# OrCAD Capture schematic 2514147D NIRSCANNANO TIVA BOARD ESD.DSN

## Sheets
1 PAGE-01  TITLE: title: ESD, NIRscan Nano Tiva Board
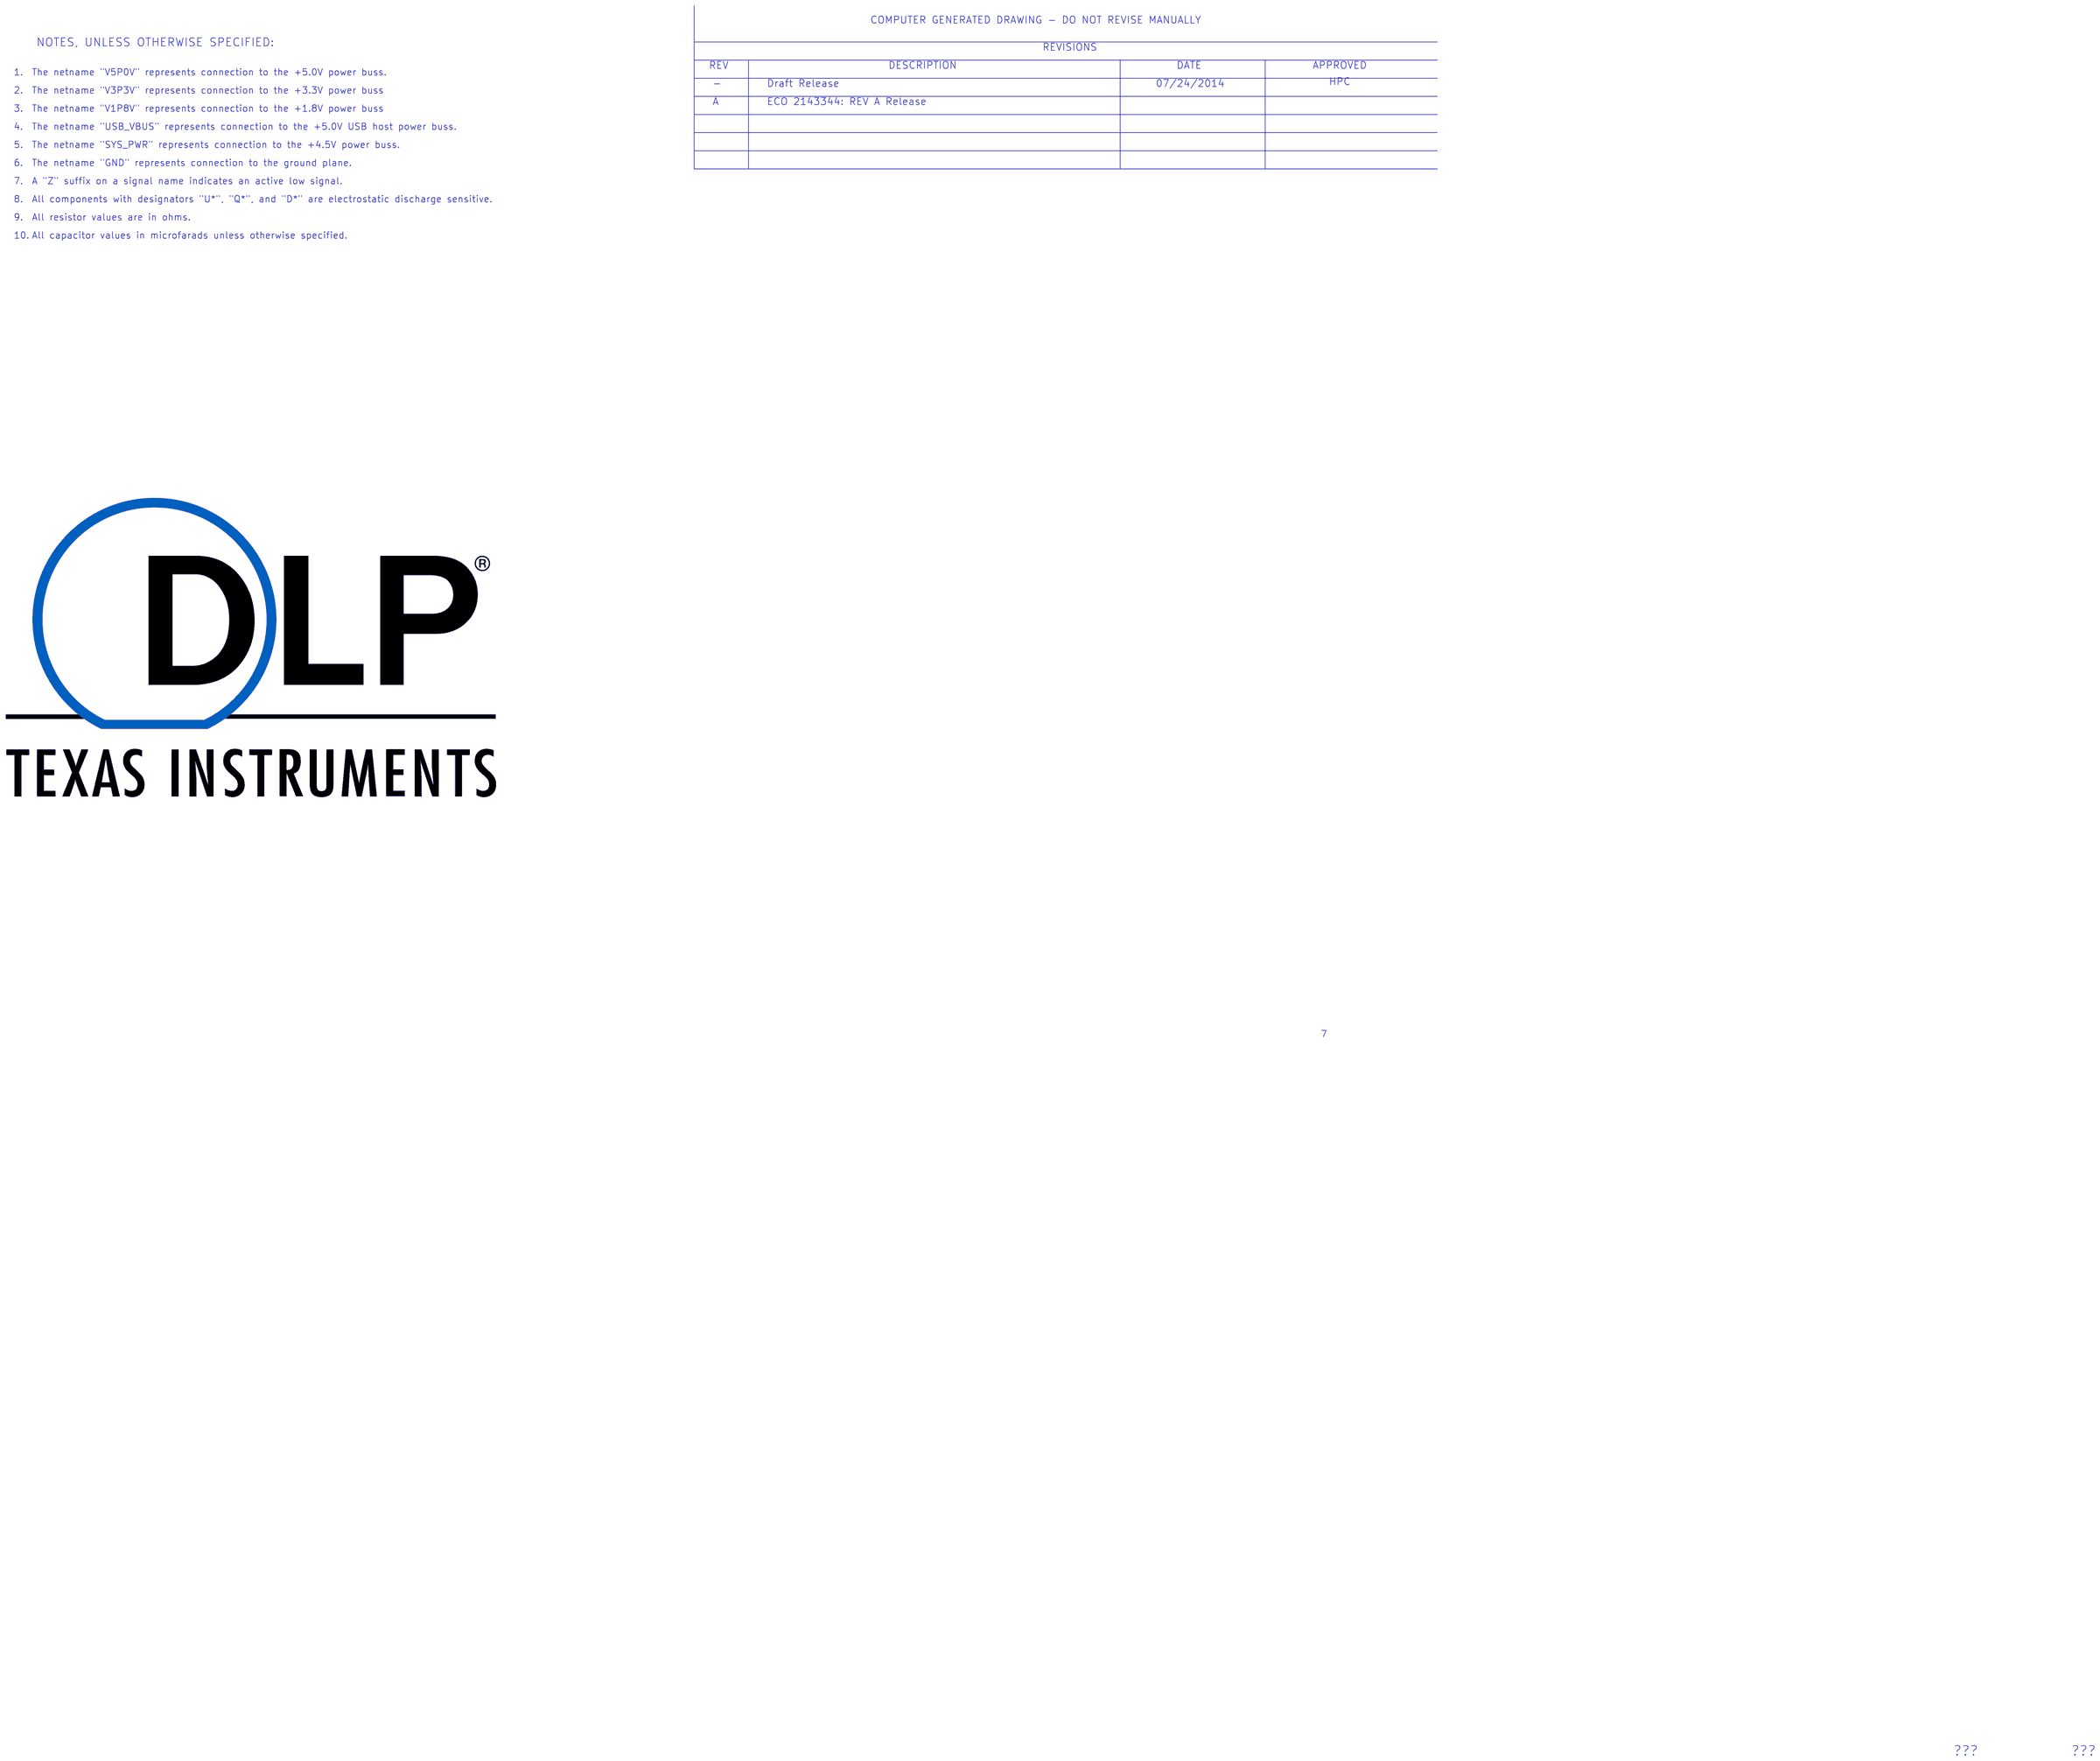
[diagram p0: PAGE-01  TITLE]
2 PAGE-02 TIVA EXTERNAL MEMORY: size A3
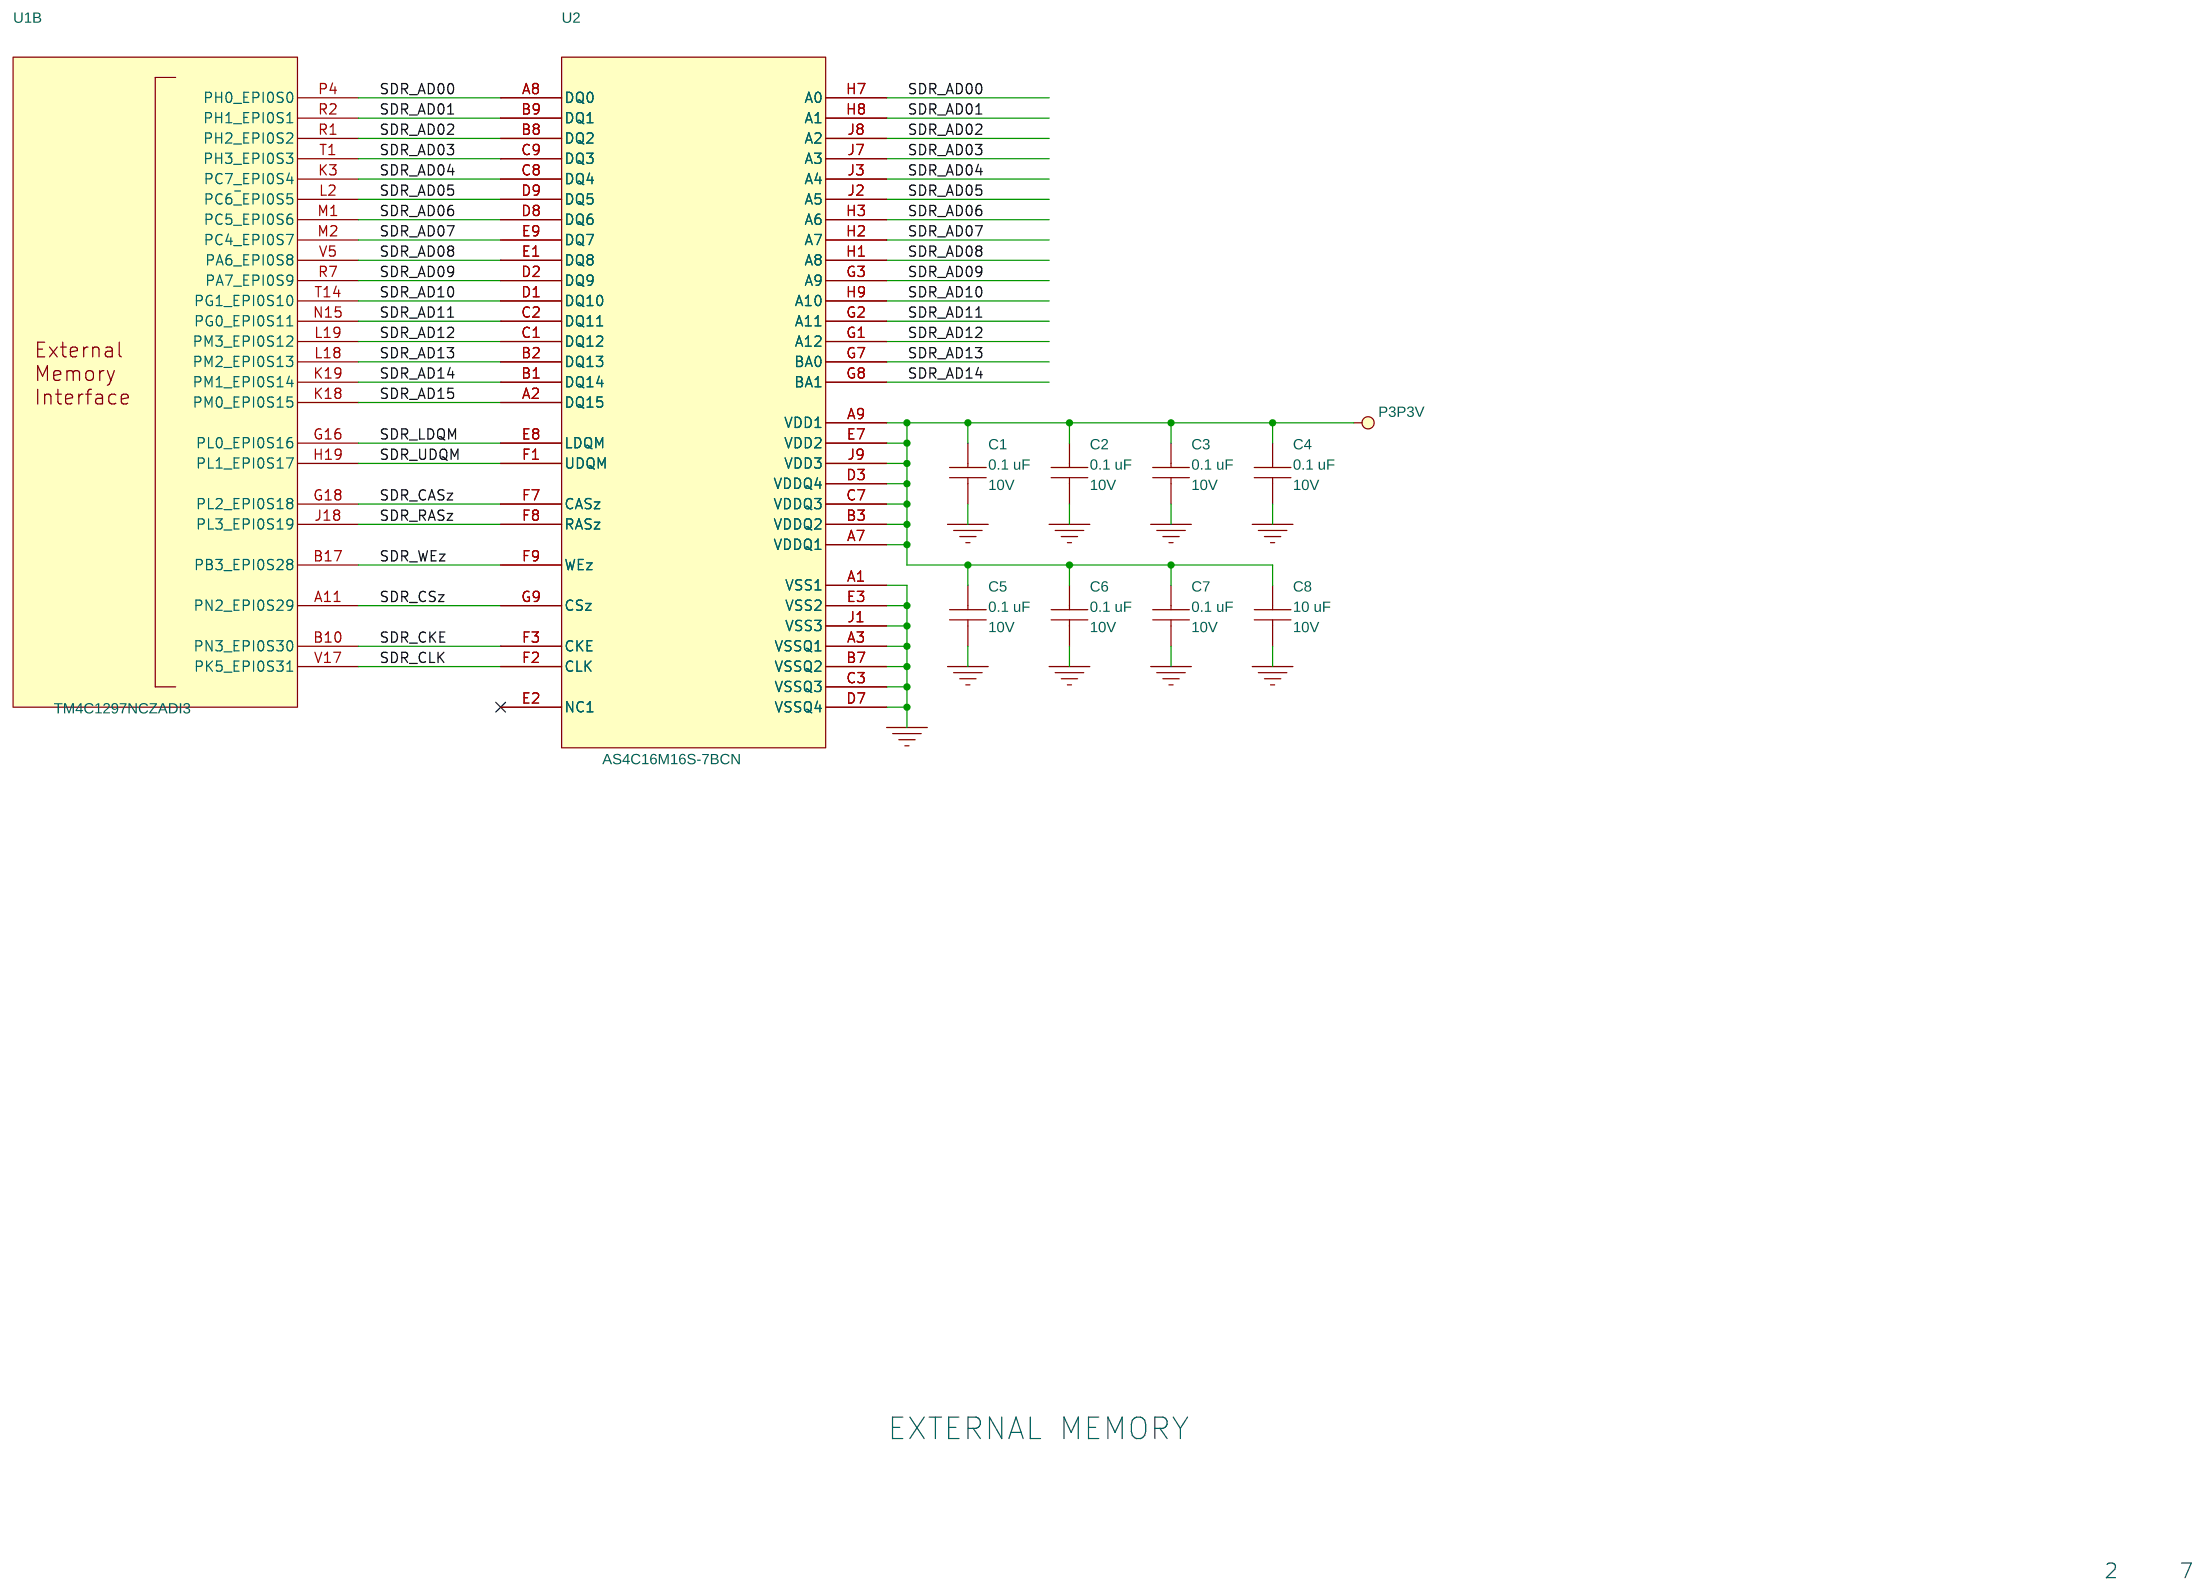
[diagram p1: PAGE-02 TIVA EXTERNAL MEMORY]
3 PAGE-03 TIVA PERIPHERALS: size A3
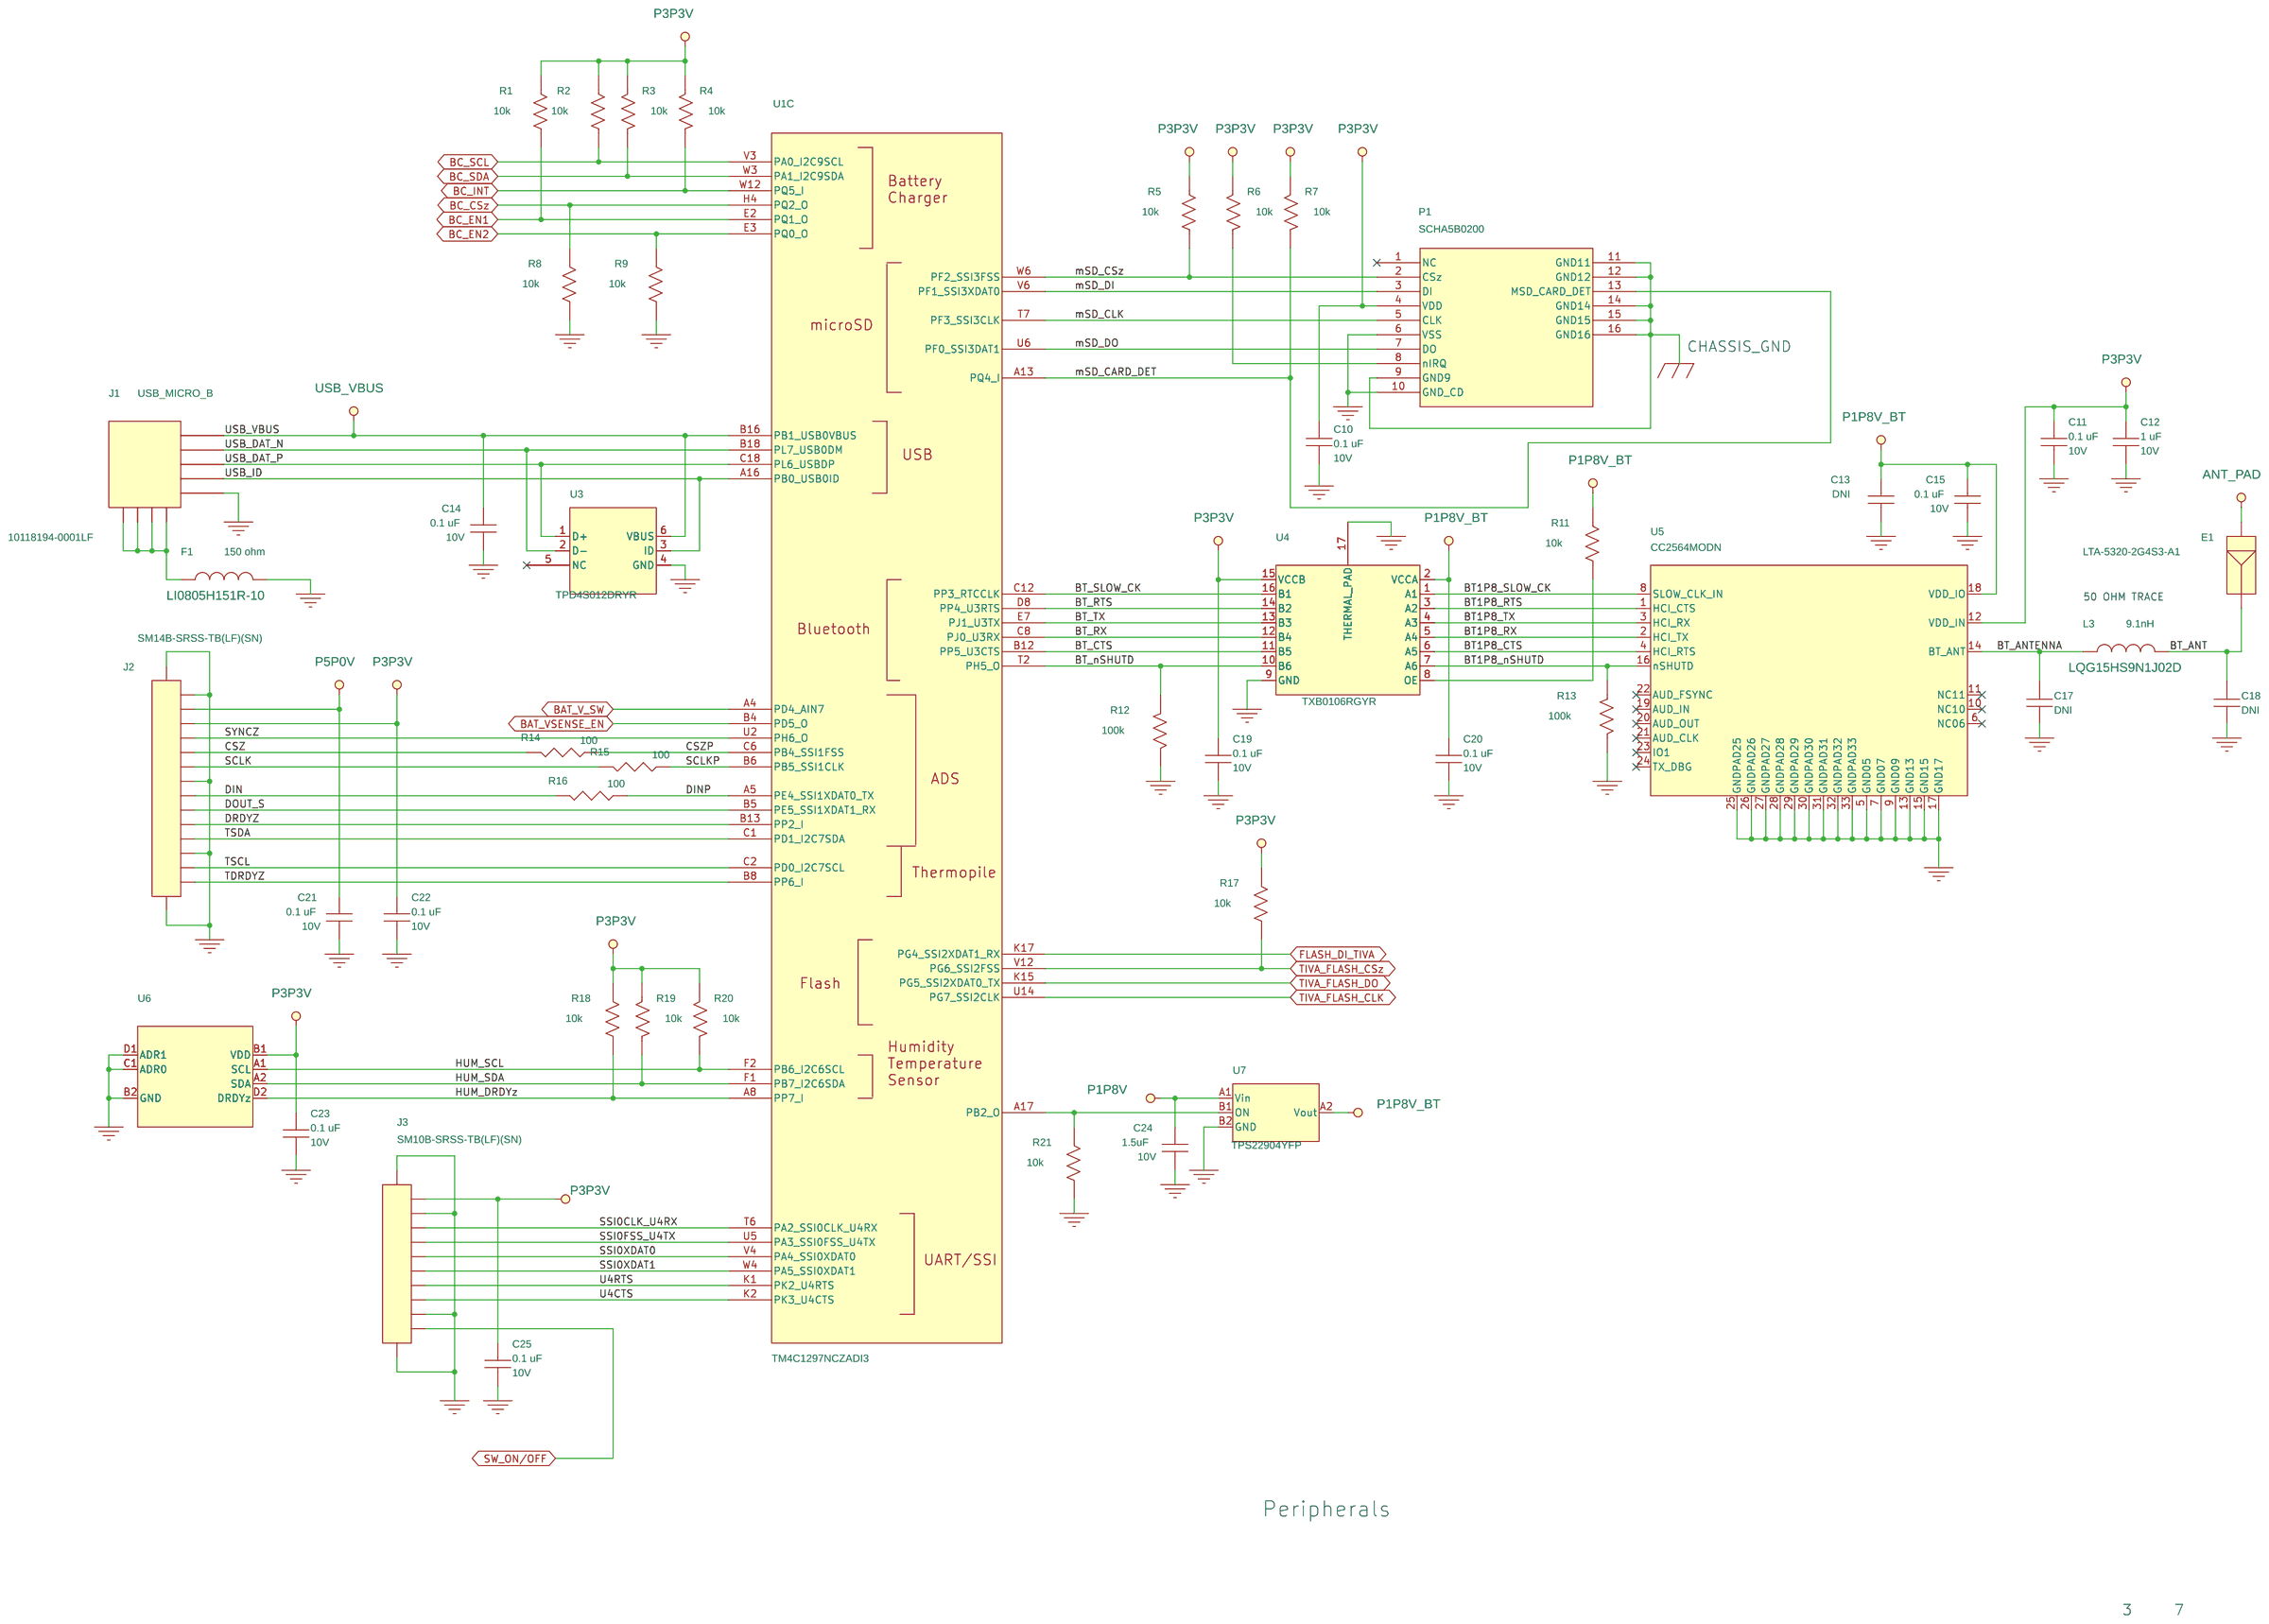
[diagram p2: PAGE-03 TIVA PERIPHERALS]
4 PAGE-04 TIVA POWER & MISC: size A3
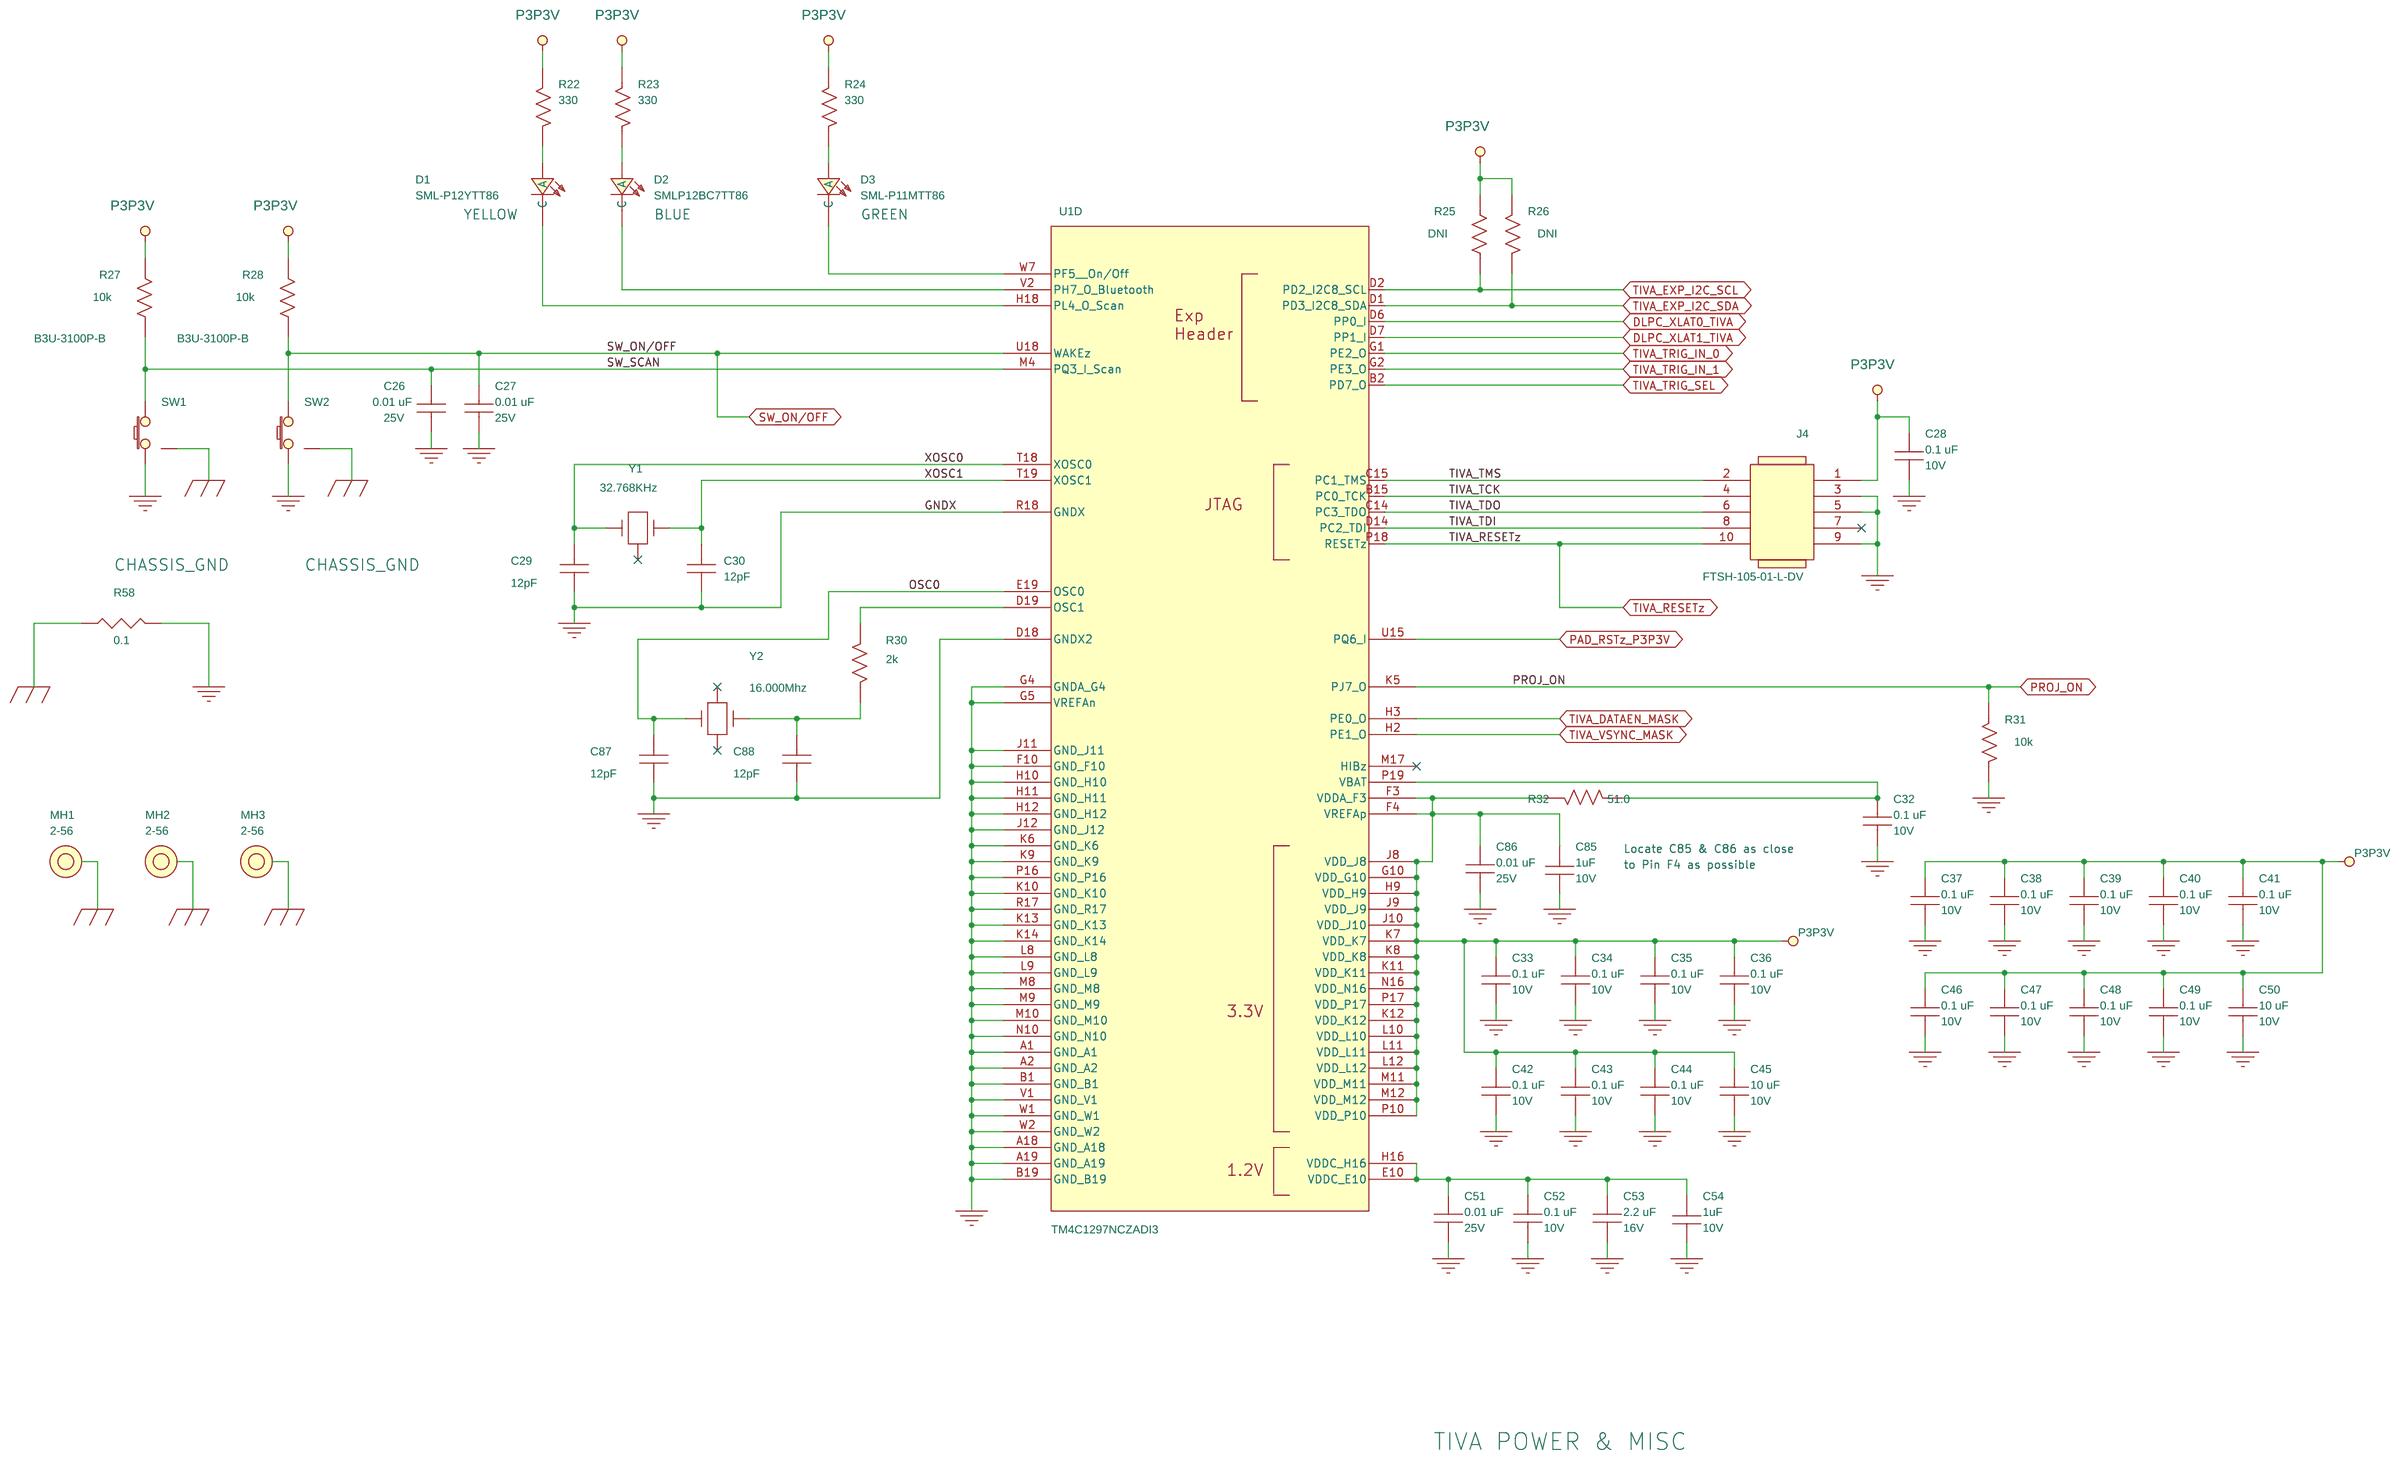
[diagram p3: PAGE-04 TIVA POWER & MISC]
5 PAGE-05 TIVA PARALLEL INTERFACE: size A3
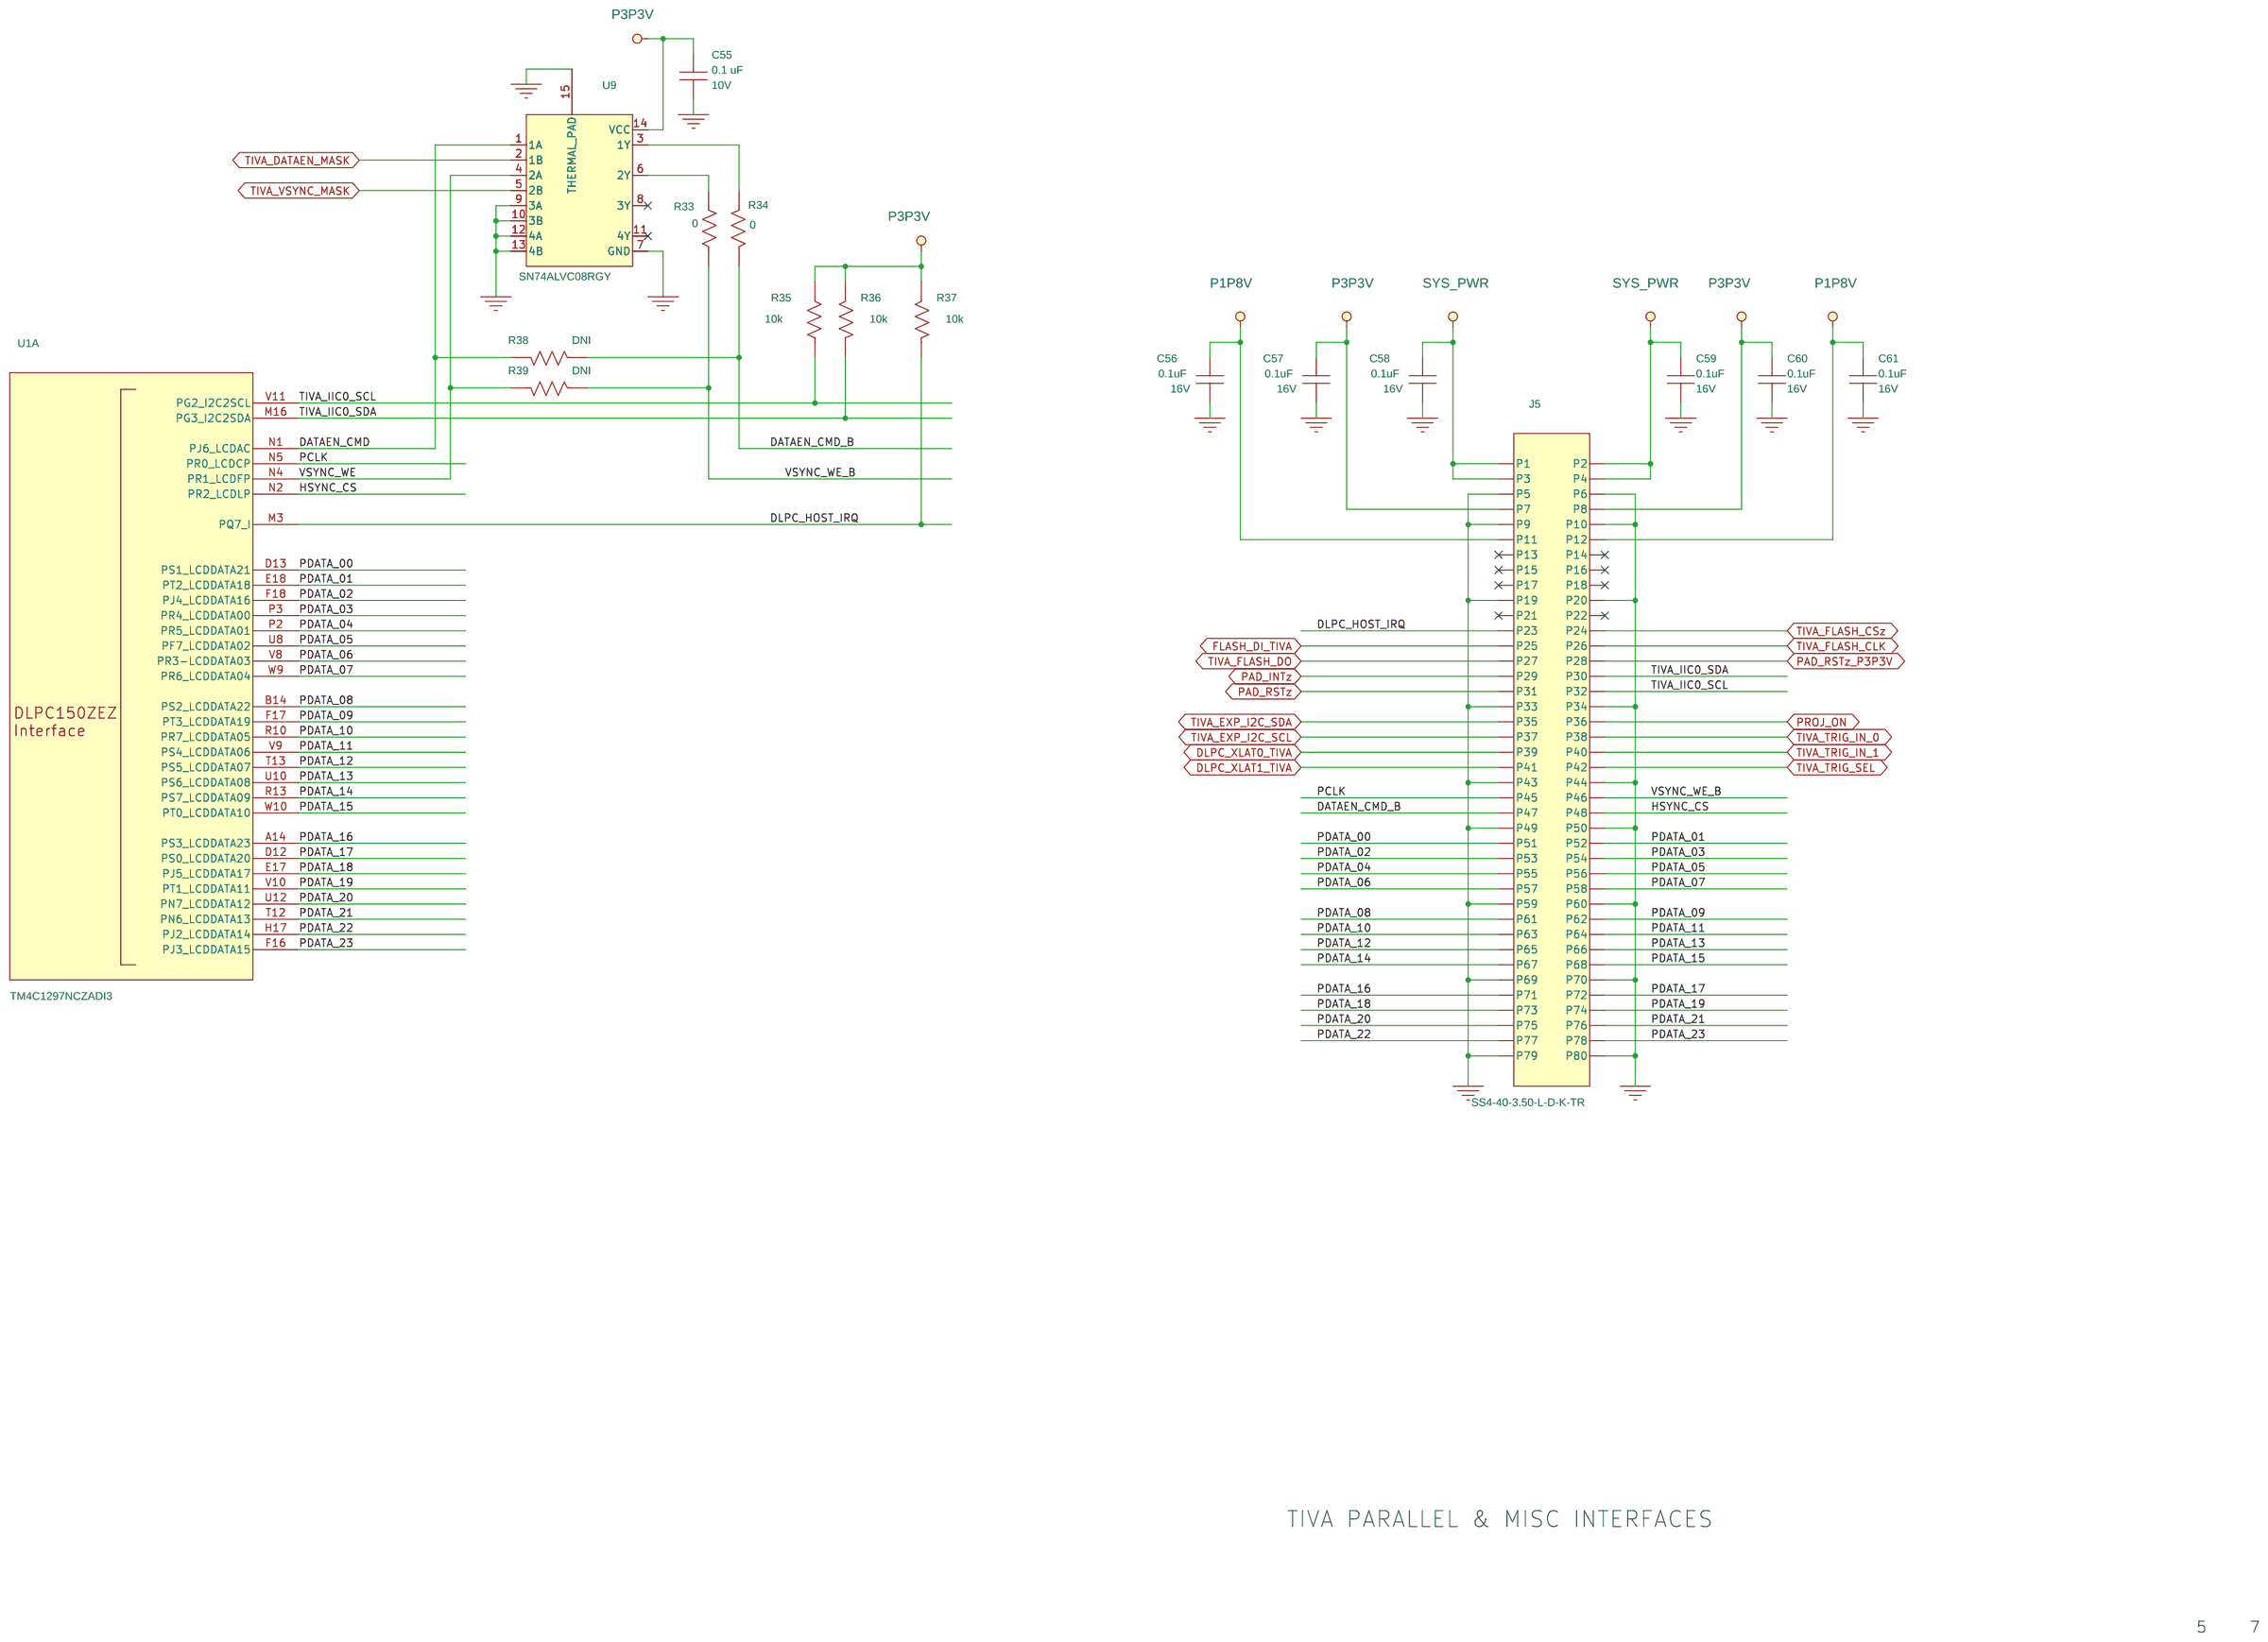
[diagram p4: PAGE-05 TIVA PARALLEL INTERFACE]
6 PAGE-06 POWER SUPPLIES: size A3
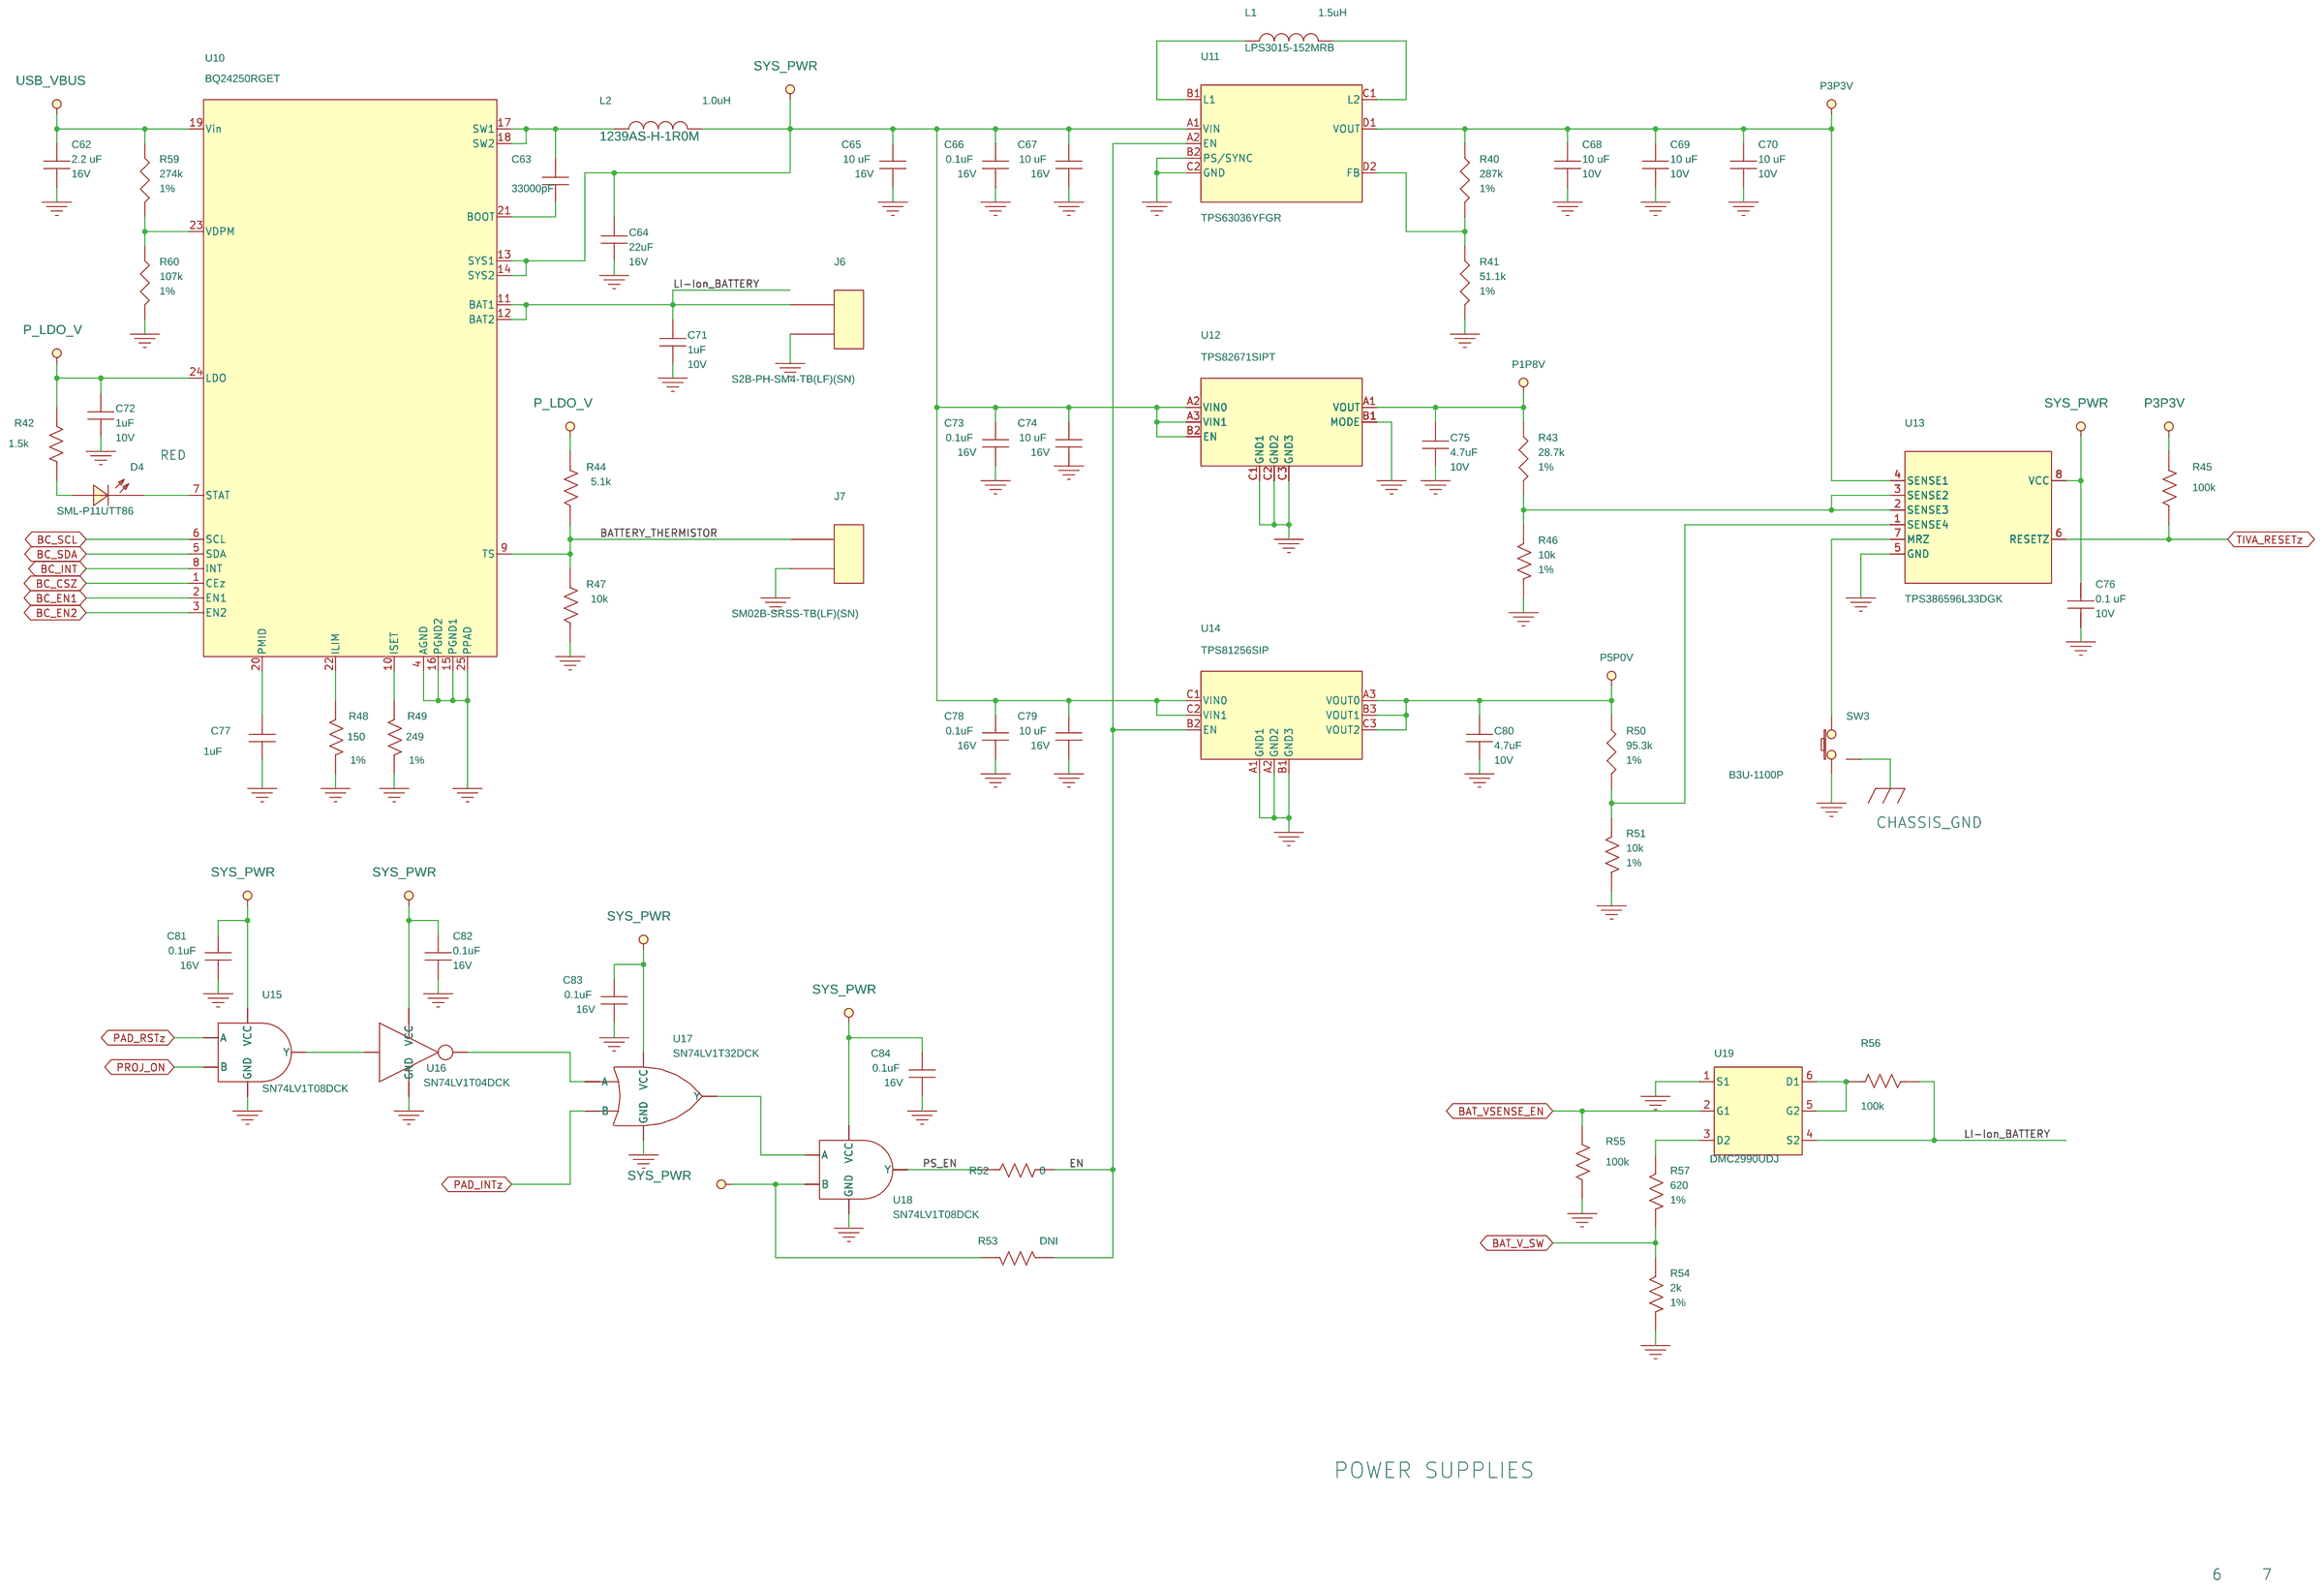
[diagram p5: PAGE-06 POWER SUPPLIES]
7 PAGE-07 REVISION HISTORY
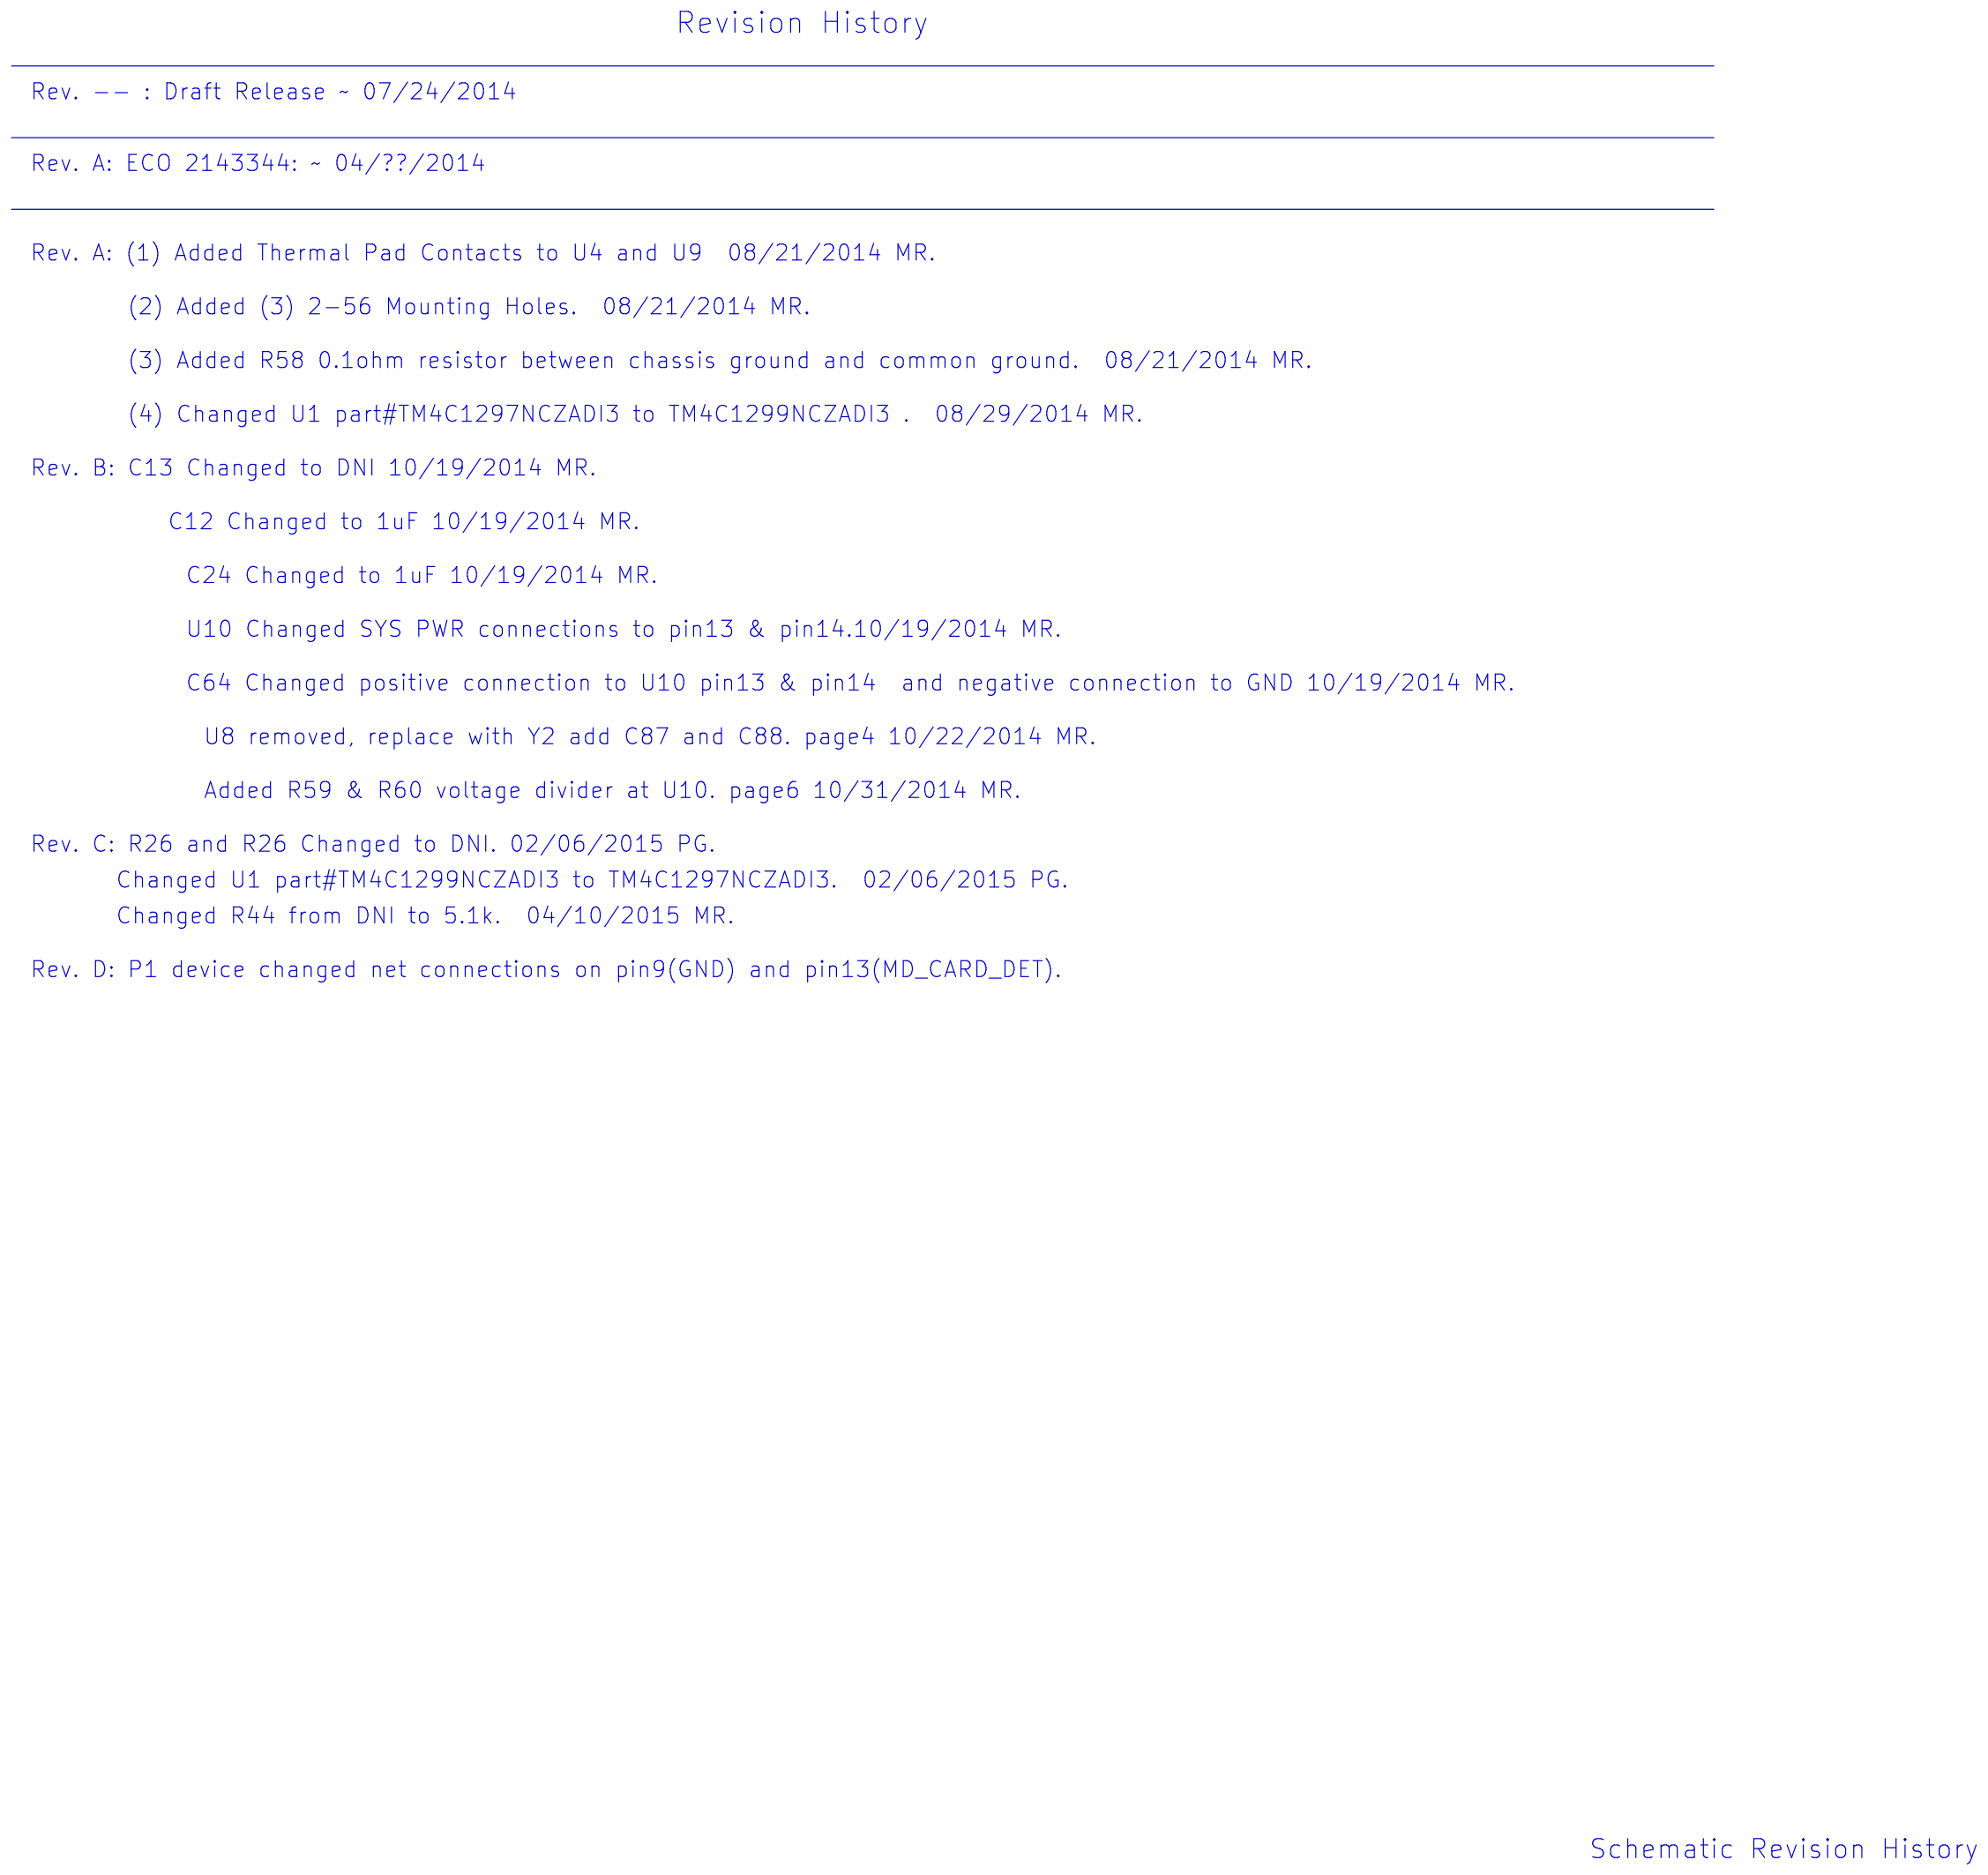
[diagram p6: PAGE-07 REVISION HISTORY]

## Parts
sheet PAGE-02 TIVA EXTERNAL MEMORY
C1  0.1 uF  [CAP_0402]
C2  0.1 uF  [CAP_0402]
C3  0.1 uF  [CAP_0402]
C4  0.1 uF  [CAP_0402]
C5  0.1 uF  [CAP_0402]
C6  0.1 uF  [CAP_0402]
C7  0.1 uF  [CAP_0402]
C8  10 uF  [CAP_0603]
U2  AS4C16M16S-7BCN  [TFBGA-54]
sheet PAGE-03 TIVA PERIPHERALS
C10  0.1 uF  [CAP_0402]
C11  0.1 uF  [CAP_0402]
C12  1 uF  [CAP_0603]
C13  DNI  [CAP_0402]
C14  0.1 uF  [CAP_0402]
C15  0.1 uF  [CAP_0402]
C17  DNI  [CAP_0201]
C18  DNI  [CAP_0201]
C19  0.1 uF  [CAP_0402]
C20  0.1 uF  [CAP_0402]
C21  0.1 uF  [CAP_0402]
C22  0.1 uF  [CAP_0402]
C23  0.1 uF  [CAP_0402]
C24  1.5uF  [CAP_0402]
C25  0.1 uF  [CAP_0402]
E1  LTA-5320-2G4S3-A1  [See_data_sheet]
F1  150 ohm  [0805]
J1  USB_MICRO_B  [See_data_sheet]
J2  SM14B-SRSS-TB(LF)(SN)  [CONN14_1p0mm]
J3  SM10B-SRSS-TB(LF)(SN)  [1p0mm_CONN10]
L3  9.1nH  [0402]
P1  SCHA5B0200  [SD-MICRO-SCHA5B0300]
R1  10k  [RES_0402]
R2  10k  [RES_0402]
R3  10k  [RES_0402]
R4  10k  [RES_0402]
R5  10k  [RES_0402]
R6  10k  [RES_0402]
R7  10k  [RES_0402]
R8  10k  [RES_0402]
R9  10k  [RES_0402]
R11  10k  [RES_0402]
R12  100k  [RES_0402]
R13  100k  [RES_0402]
R14  100  [RES_0402]
R15  100  [RES_0402]
R16  100  [RES_0402]
R17  10k  [RES_0402]
R18  10k  [RES_0402]
R19  10k  [RES_0402]
R20  10k  [RES_0402]
R21  10k  [RES_0402]
U1  TM4C1297NCZADI3  [ZAD_212]  (sections A,B,C,D)
U3  TPD4S012DRYR  [6-SON_DRY]
U4  TXB0106RGYR  [16-QFN]
U5  CC2564MODN  [TSSOP_38]
U6  HDC1000  [WCSP-8]
U7  TPS22904YFP  [DSBGA]
sheet PAGE-04 TIVA POWER & MISC
C26  0.01 uF  [CAP_0402]
C27  0.01 uF  [CAP_0402]
C28  0.1 uF  [CAP_0402]
C29  12pF  [CAP_0402]
C30  12pF  [CAP_0402]
C32  0.1 uF  [CAP_0402]
C33  0.1 uF  [CAP_0402]
C34  0.1 uF  [CAP_0402]
C35  0.1 uF  [CAP_0402]
C36  0.1 uF  [CAP_0402]
C37  0.1 uF  [CAP_0402]
C38  0.1 uF  [CAP_0402]
C39  0.1 uF  [CAP_0402]
C40  0.1 uF  [CAP_0402]
C41  0.1 uF  [CAP_0402]
C42  0.1 uF  [CAP_0402]
C43  0.1 uF  [CAP_0402]
C44  0.1 uF  [CAP_0402]
C45  10 uF  [CAP_0603]
C46  0.1 uF  [CAP_0402]
C47  0.1 uF  [CAP_0402]
C48  0.1 uF  [CAP_0402]
C49  0.1 uF  [CAP_0402]
C50  10 uF  [CAP_0603]
C51  0.01 uF  [CAP_0402]
C52  0.1 uF  [CAP_0402]
C53  2.2 uF  [CAP_0402]
C54  1uF  [CAP_0402]
C85  1uF  [CAP_0402]
C86  0.01 uF  [CAP_0402]
C87  12pF  [CAP_0402]
C88  12pF  [CAP_0402]
D1  SML-P12YTT86  [LED_0402]
D2  SMLP12BC7TT86  [LED_0402]
D3  SML-P11MTT86  [LED_0402]
J4  FTSH-105-01-L-DV  [0p050_2X5]
MH1  2-56  [pl_mtg_2_56_89d_260c]
MH2  2-56  [pl_mtg_2_56_89d_260c]
MH3  2-56  [pl_mtg_2_56_89d_260c]
R22  330  [RES_0402]
R23  330  [RES_0402]
R24  330  [RES_0402]
R25  DNI  [RES_0402]
R26  DNI  [RES_0402]
R27  10k  [RES_0402]
R28  10k  [RES_0402]
R30  2k  [RES_0402]
R31  10k  [RES_0402]
R32  51.0  [RES_0402]
R58  0.1  [0805]
SW1  B3U-3100P-B  [Micro_Switch]
SW2  B3U-3100P-B  [Micro_Switch]
Y1  32.768KHz  [CMR200T]
Y2  16.000Mhz  [CMR200T]
sheet PAGE-05 TIVA PARALLEL INTERFACE
C55  0.1 uF  [CAP_0402]
C56  0.1uF  [CAP_0402]
C57  0.1uF  [CAP_0402]
C58  0.1uF  [CAP_0402]
C59  0.1uF  [CAP_0402]
C60  0.1uF  [CAP_0402]
C61  0.1uF  [CAP_0402]
J5  SS4-40-3.50-L-D-K-TR  [CONN60_MEC8_M]
R33  0  [RES_0201]
R34  0  [RES_0201]
R35  10k  [RES_0402]
R36  10k  [RES_0402]
R37  10k  [RES_0402]
R38  DNI  [RES_0402]
R39  DNI  [RES_0402]
U9  SN74ALVC08RGY  [RGY]
sheet PAGE-06 POWER SUPPLIES
C62  2.2 uF  [CAP_0402]
C63  33000pF  [CAP_0402]
C64  22uF  [CAP_0805]
C65  10 uF  [CAP_0603]
C66  0.1uF  [CAP_0402]
C67  10 uF  [CAP_0603]
C68  10 uF  [CAP_0603]
C69  10 uF  [CAP_0603]
C70  10 uF  [CAP_0603]
C71  1uF  [CAP_0402]
C72  1uF  [CAP_0402]
C73  0.1uF  [CAP_0402]
C74  10 uF  [CAP_0603]
C75  4.7uF  [CAP_0402]
C76  0.1 uF  [CAP_0402]
C77  1uF  [CAP_0402]
C78  0.1uF  [CAP_0402]
C79  10 uF  [CAP_0603]
C80  4.7uF  [CAP_0402]
C81  0.1uF  [CAP_0402]
C82  0.1uF  [CAP_0402]
C83  0.1uF  [CAP_0402]
C84  0.1uF  [CAP_0402]
D4  SML-P11UTT86  [LED_0402]
J6  S2B-PH-SM4-TB(LF)(SN)  [CONN_2POS_2P0mm_RA]
J7  SM02B-SRSS-TB(LF)(SN)  [CONN_2POS_1P0mm_RA]
L1  1.5uH  [3p3mm_x_3p3mm]
L2  1.0uH  [2520]
R40  287k  [RES_0402]
R41  51.1k  [RES_0402]
R42  1.5k  [RES_0402]
R43  28.7k  [RES_0402]
R44  5.1k  [RES_0402]
R45  100k  [RES_0402]
R46  10k  [RES_0402]
R47  10k  [RES_0402]
R48  150  [RES_0402]
R49  249  [RES_0402]
R50  95.3k  [RES_0402]
R51  10k  [RES_0402]
R52  0  [RES_0201]
R53  DNI  [RES_0402]
R54  2k  [RES_0402]
R55  100k  [RES_0402]
R56  100k  [RES_0402]
R57  620  [RES_0402]
R59  274k  [RES_0402]
R60  107k  [RES_0402]
SW3  B3U-1100P  [Micro_Switch]
U10  BQ24250RGET  [24VQFN]
U11  TPS63036YFGR  [8WCSP]
U12  TPS82671SIPT  [8USIP]
U13  TPS386596L33DGK  [DGK]
U14  TPS81256SIP  [9USIP]
U15  SN74LV1T08DCK  [DCK]
U16  SN74LV1T04DCK  [DCK]
U17  SN74LV1T32DCK  [DCK]
U18  SN74LV1T08DCK  [DCK]
U19  DMC2990UDJ  [SOT963]

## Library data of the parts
C1-C7 C10 C11 C14 C15 C19-C23 C25 C28 C32-C44 C46-C49 C52 C55 C76 = CAP_NP: CAP CER 0.1UF 10V 10% X7R 0402; MFG: KEMET; Manufacturer: KEMET; Part Number: C0402C104K8RACTU; RATING: 10V; SOURCE: DIGI 399-3520-1-ND; TOLERANCE: 10%; Type: X7R
C8 C45 C50 C68-C70 = CAP_NP: CAP CER 10UF 10V 10% X5R 0603; MFG: TDK; Manufacturer: TDK; Part Number: C1608X5R1A106K080AC; RATING: 10V; SOURCE: DIGI 445-7486-1-ND; TOLERANCE: 10%; Type: X5R
U2 = AS4C16M16S-7BCN
C12 = CAP_NP: CAP CER 10UF 10V 10% X5R 0603; MFG: TDK; Manufacturer: TDK; Part Number: C1608X5R1A105K080AC; RATING: 10V; SOURCE: DIGI 445-1321-1-ND; TOLERANCE: 10%; Type: X5R
C13 = CAP_NP: CAP CER 10UF 6.3V 20% X5R 0402; MFG: TDK; Manufacturer: TDK; Part Number: C1005X5R0J106M050BC; RATING: 6.3V; SOURCE: DIGI 445-8920-1-ND; TOLERANCE: 20%; Type: X5R
C17 C18 = CAP_18PF_COG_50V_5%_0402: CAP CER ??PF 25V 0.5% NP0 0201; Manufacturer: TDK; Part Number: ??; RATING: 25V; SOURCE: DIGI ??; TOLERANCE: 0.5%; Type: NPO
C24 = CAP_NP: CAP CER 1.5uF 10V 10% X5R 0402; MFG: TDK; Manufacturer: TDK; Part Number: C1005X5R1A155K050BC; RATING: 10V; SOURCE: DIGI 445-7390-1-ND; TOLERANCE: 10%; Type: X5R
E1 = ANTENNA_CHIP: ANTENNA CHIP DIELECTRIC 2450MHZ; Manufacturer: Mag Layers; SOURCE: Mag Layers; Vendor: Mag Layers
F1 = PAS,INDUCTOR,_large: FERRITE 800mA 150 ohm 0402; Family: passive; Index PN: 1149; Lead Style: SMT; MFG: MURATA; Manufacturer: MURATA; P/D_NUM: LI0805H151R-10; Part Number: LI0805H151R-10; Part Specific: ?; RATING: 300mA; SOURCE: DIGI 240-2384-1-ND; Type: ferrite; VENDOR: DIGI 240-2384-1-ND
J1 = CON_USB_MICRO: CONN RCPT MICRO USB B 5POS THRU HOLE R/A; Manufacturer: FCI; Part Number: 10118194-0001LF; SOURCE: DIGI 609-4618-1-ND
J2 = CONN_14n_1p0mm: CONN HEADER SH 14POS TOP 1MM TIN; Manufacturer: JST; SOURCE: DIGI 455-1800-1-ND
J3 = CONN_10n_1p0mm: CONN HEADER SH 10POS SIDE 1MM TIN; Manufacturer: JST; SOURCE: DIGI 455-1810-1-ND
L3 = PAS,INDUCTOR,_large: INDUCTOR 9.1nH 300mA 0402; Family: passive; Index PN: 1149; Lead Style: SMT; MFG: MURATA; Manufacturer: MURATA; P/D_NUM: LQG15HS9N1J02D; Part Number: LQG15HS9N1J02D; Part Specific: ?; RATING: 300mA; SOURCE: RRFPD 1239AS-H-1R0M=P3; Type: inductor; VENDOR: DIGI 490-8390-1-ND
P1 = microSD_CONN_0: CONN MICRO SD CARD SOCKET; SOURCE: Mouser 688-SCHA5B0200
R1-R6 R8 R9 R11 R17-R21 R26-R28 R35 R46 = PAS,R,large: RES 10K OHM 1/10W 1% 0402 SMD; DigiKey: P10.0KLCT-ND; DigiReel: P10.0KLDKR-ND; Family: passive; Index PN: 680; Lead Style: SMT; MFG: Panasonic; Manufacturer: Panasonic; Material: chip; P/D_NUM: ERJ-2RKF1002X; Part Number: ERJ-2RKF1002X; Power: 1/16W; SOURCE: DIGI P10.0KLCT-ND; Tolerance: 1%; Type: resistor; VPC: 1/16W; Vendor: Panasonic
R7 R25 R31 R36 R37 R51 = PAS,R,large: RES 10K OHM 1/10W 1% 0402 SMD; Family: passive; Index PN: 680; Lead Style: SMT; MFG: Panasonic; Manufacturer: Panasonic; Material: chip; P/D_NUM: ERJ-2RKF1002X; Part Number: ERJ-2RKF1002X; Power: 1/16W; SOURCE: DIGI P10.0KLCT-ND; Tolerance: 1%; Type: resistor; VPC: 1/16W; Vendor: Panasonic
R12 R13 R45 R55 R56 = PAS,R,large: RES 100K OHM 1/10W 1% 0402 SMD; Family: passive; Index PN: 712; Lead Style: SMT; MFG: Panasonic; Manufacturer: Panasonic; Material: chip; P/D_NUM: ERJ-2RKF1003X; Part Number: ERJ-2RKF1003X; Power: 1/16W; SOURCE: DIGI P100KLCT-ND; TOLERANCE: 1%; Type: resistor; VPC: 1/16W; Vendor: Panasonic
R14-R16 = 1KR2F: RES 100 OHM 1/16W 1% 0402 SMD; MFG: Yageo; Manufacturer: ROHM; Manufacturer Part Number: MCR01MRTF1000; Part Number: MCR01MRTF1000; RATING: 1/16W; SOURCE: DIGI RHM100CDCT-ND; TOLERANCE: 1%
U1 = TM4C1297NCZADI3_7
U3 = TPD4S012_small: Manufacturer: Texas Instruments; SOURCE: DIGI 296-24244-1-ND
U4 = TXB0106RGYR_0
U5 = CC2564MODN
U6 = HDC1000
U7 = TPS22904
C26 C27 C51 C86 = CAP_NP: CAP CER 10000PF 25V 10% X5R 0402; MFG: KEMET; Manufacturer: TDK; Part Number: C1005X5R1E103K050BA; RATING: 25V; SOURCE: DIGI 445-7386-1-ND; TOLERANCE: 10%; Type: X5R
C29 C87 C88 = CAP_18PF_COG_50V_5%_0402: CAP CER 12PF 50V 5% NP0 0402; Desc: ?; Manufacturer: Murata; Part Number: GRM1555C1H120JA01D; RATING: 50V; SOURCE: DIGI 490-5924-1-ND; TOLERANCE: 5%; Type: NPO
C30 = CAP_18PF_COG_50V_5%_0402: CAP CER 12PF 50V 5% NP0 0402; Desc: CAP CER 18PF 50V 5% NP0 0402; Manufacturer: Murata; Part Number: GRM1555C1H120JA01D; RATING: 50V; SOURCE: DIGI 490-5924-1-ND; TOLERANCE: 5%; Type: NPO
C53 C62 = CAP_NP: CAP CER 2.2UF 16V 10% X5R 0402; MFG: MURATA; Manufacturer: TDK; Part Number: C1005X5R1C225K050BC; RATING: 16V; SOURCE: DIGI 445-9085-1-ND; TOLERANCE: 10%; Type: X5R
C54 C71 C72 C77 C85 = CAP_18PF_COG_50V_5%_0402: CAP CER 1UF 10V 20% X5R 0402; Manufacturer: TDK; Part Number: C1005X5R1A105M050BB; RATING: 10V; SOURCE: DIGI 445-4991-1-ND; TOLERANCE: 20%; Type: X5R
D1 = LED_v: LED YELLOW 0.2MM 130MCD 0402 SMD; Manufacturer: ROHM; SOURCE: DIGI 511-1595-1-ND
D2 = LED_v: LED 0402 BLUE 465NM TRANSPARENT; Manufacturer: ROHM; SOURCE: DIGI 511-1615-1-ND
D3 = LED_v: LED 0402 GREEN 54MW 20MA SMD; Manufacturer: ROHM; SOURCE: DIGI 511-1652-1-ND
J4 = HEADER_2X5_JTAG: 1.27mm SMT MICRO HEADER
MH1-MH3 = PL_MTG_2-56
R22-R24 = PAS,R,large: RES 300 OHM 1/10W 1% 0402 SMD; Family: passive; Index PN: 680; Lead Style: SMT; MFG: Panasonic; Manufacturer: Panasonic; Material: chip; P/D_NUM: ERJ-2RKF3000X; Part Number: ERJ-2RKF3000X; Power: 1/16W; SOURCE: DIGI P300LCT-ND; Tolerance: 1%; Type: resistor; VPC: 1/16W; Vendor: Panasonic
R30 = PAS,R,large: RES 2K OHM 1/10W 1% 0402 SMD; Family: passive; Index PN: 1167; Lead Style: SMT; Manufacturer: Panasonic; Part Number: ERJ-2RKF2001X; SOURCE: DIGI P2.00KLCT-ND; TOLERANCE: 1%; Type: resistor; VENDOR: Panasonic
R32 = PAS,R,large: RES 50.0 OHM 1/10W 1% 0402 SMD; Family: passive; Index PN: 1167; Lead Style: SMT; Manufacturer: Panasonic; Part Number: ERJ-2RKF51R0X; SOURCE: DIGI P51.0LCT-ND; TOLERANCE: 1%; Type: resistor; VENDOR: Panasonic
R58 = RES0805
SW1 SW2 = SWITCH,PUSH_BUTTON_SPST: SWITCH TACTILE SPST-NO 0.05A 12V; Manufacturer: Omron; RATING: 12VDC; SOURCE: DIGI SW1103CT-ND
Y1 = CRYS_32_768KHz: CRYSTAL 32.768KHZ 7PF SMD; Manufacturer: Citizen; Part Number: CMR200T-32.768KDZYT; SOURCE: DIGI 300-8736-1-ND
Y2 = CRYS_32_0: CRYSTAL 16.00MHZ 0.75mm SMD; Manufacturer: NDK; Mfr: NDK; MfrNum: NX3225GA- 16.000MHZ- STD-CRG-2; Part Number: NX3225GA- 16.000MHZ- STD-CRG-2; PartName: CRYSTAL 16.00MHZ 0.75mm SMD; SOURCE: DIGI 644-1157-1-ND; Vendor: NDK
C56-C61 C66 C73 C78 C81-C84 = CAP_NP: CAP CER 0.1UF 16V 10% X7R 0402; MFG: Murata; Manufacturer: Murata; Part Number: GRM155R71C104KA88D; RATING: 16V; SOURCE: DIGI 490-3261-1-ND; TOLERANCE: 10%; Type: X7R; VPC: 16V
J5 = CONN80_MEC8_M_0_SOCKET
R33 R34 R52 = PAS,R,large: RES 0.0 OHM 1/20W JUMP 0201 SMD; Family: passive; Index PN: 1178; Lead Style: SMT; MFG: Panasonic; Manufacturer: Panasonic; Material: chip; P/D_NUM: ERJ-1GE0R00C; Part Number: ERJ-1GE0R00C; SOURCE: DIGI P0.0AGCT-ND; Type: resistor; VENDOR: Panasonic; VPC: 1/20W
R38 R39 R53 = PAS,R,large: RES ?? OHM 1/10W 1% 0402 SMD; Family: passive; Index PN: 687; Lead Style: SMT; MFG: Panasonic; Material: chip; Part Specific: RES 0.0 OHM 1/16W 0402 SMD; Power: 1/16W; TOLERANCE: 1%; Type: resistor; VPC: 1/16W; Vendor: Panasonic
U9 = SN74ALVC08_0: IC GATE AND 4CH 2-INP 14-VQFN; Source: DIGI 296-13918-1-ND
C63 = CAP_18PF_COG_50V_5%_0402: CAP CER 0.033UF 50V 10% X5R 0402; Manufacturer: TDK; Part Number: C1005X5R1H333K050BB; RATING: 50V; SOURCE: DIGI 445-1238-1-ND; TOLERANCE: 10%; Type: X5R
C64 = CAP_18PF_COG_50V_5%_0402: CAP CER 22UF 16V 20% X5R 0805; Desc: ?; Manufacturer: TDK; Part Number: C2012X5R1C226M125AC; RATING: 16V; SOURCE: DIGI 445-7647-1-ND; TOLERANCE: 20%; Type: X5R
C65 C67 C74 C79 = CAP_NP: CAP CER 10UF 16V 20% X5R 0603; MFG: TDK; Manufacturer: TDK; Part Number: C1608X5R1C106M080AB; RATING: 16V; SOURCE: DIGI 445-9065-1-ND; TOLERANCE: 20%; Type: X5R
C75 C80 = CAP_18PF_COG_50V_5%_0402: CAP CER 4.7UF 10V 10% X5R 0402; Manufacturer: TDK; Part Number: C1005X5R1A475K050BC; RATING: 10V; SOURCE: DIGI 445-13820-1-ND; TOLERANCE: 10%; Type: X5R
D4 = LED_LTST-C150CKT_2: LED 0402 RED 50MW 20MA SMD; Manufacturer: ROHM; SOURCE: DIGI 511-1653-1-ND
J6 = CON2: CONN HEADER 2 POS 2.0MM R/A SMD; Manufacturer: JST; Source: DIGI 455-1749-1-ND
J7 = CON2: CONN HEADER 2 POS 1.0MM R/A SMD; Manufacturer: JST; Source: DIGI 455-1802-1-ND
L1 = INDUCTOR: INDUCTOR 1.5uH SHIELDED POWER; Manufacturer: Coilcraft; Part Number: LPS3015-152MRB; SOURCE: Mouser 994-LPS3015-152MRB
L2 = PAS,INDUCTOR,_large: INDUCTOR 1uH 20% 2520; Family: passive; Index PN: 1149; Lead Style: SMT; MFG: TOKO; Manufacturer: TOKO; P/D_NUM: LQM2HPN2R2MG0L; Part Number: 1239AS-H-1R0M; Part Specific: ?; RATING: 3AMP; SOURCE: RRFPD 1239AS-H-1R0M=P3; Tolerance: 20%; Type: inductor; VENDOR: ?
R40 = RESISTOR: RES 287K OHM 1/10W 1% 0402 SMD; Manufacturer: Panasonic; P/D_NUM: ERJ-2RKF2873X; Part Number: ERJ-2RKF2873X; SOURCE: DIGI P287KLCT-ND; TOLERANCE: 1%
R41 = RESISTOR: RES 51.1K OHM 1/10W 1% 0402 SM; Manufacturer: Panasonic; P/D_NUM: P51.1KLCT-ND; Part Number: P51.1KLCT-ND; SOURCE: DIGI P51.1KLCT-ND; TOLERANCE: 1%
R42 = PAS,R,large: RES 1.5K OHM 1/10W 1% 0402 SMD; Family: passive; Index PN: 680; Lead Style: SMT; MFG: Panasonic; Manufacturer: Panasonic; Material: chip; P/D_NUM: ERJ-2RKF1501X; Part Number: ERJ-2RKF1501X; Power: 1/16W; SOURCE: DIGI P1.50KLCT-ND; Tolerance: 1%; Type: resistor; VPC: 1/16W; Vendor: Panasonic
R43 = RESISTOR: RES 28.7K OHM 1/10W 1% 0402 SMD; Manufacturer: Panasonic; P/D_NUM: ERJ-2RKF2872X; Part Number: ERJ-2RKF2872X; SOURCE: DIGI P28.7KLCT-ND; TOLERANCE: 1%
R44 = PAS,R,large: RES SMD 5.1K OHM 5% 1/10W 0402; Family: passive; Index PN: 687; Lead Style: SMT; MFG: Panasonic; Material: chip; Part Number: ERJ-2GEJ512X; Part Specific: RES SMD 5.1K OHM 5% 1/10W 0402; Power: 1/10W; TOLERANCE: 5%; Type: resistor; VPC: 1/10W; Vendor: Panasonic
R47 = PAS,R,large: RES 10k OHM 1/10W 1% 0402 SMD; Family: passive; Index PN: 687; Lead Style: SMT; MFG: Panasonic; Material: chip; Part Number: ERJ-2RKF1002X; Part Specific: RES 10k OHM 1/16W 0402 SMD; Power: 1/16W; TOLERANCE: 1%; Type: resistor; VPC: 1/16W; Vendor: Panasonic
R48 = PAS,R,large: RES 150 OHM 1/10W 1% 0402 SMD; Family: passive; Index PN: 680; Lead Style: SMT; MFG: Panasonic; Manufacturer: Panasonic; Material: chip; P/D_NUM: ERJ-2RKF1500X; Part Number: ERJ-2RKF1500X; Power: 1/16W; SOURCE: DIGI P150LCT-ND; Tolerance: 1%; Type: resistor; VPC: 1/16W; Vendor: Panasonic
R49 = PAS,R,large: RES 249 OHM 1/10W 1% 0402 SMD; Family: passive; Index PN: 680; Lead Style: SMT; MFG: Panasonic; Manufacturer: Panasonic; Material: chip; P/D_NUM: ERJ-2RKF2490X; Part Number: ERJ-2RKF2490X; Power: 1/16W; SOURCE: DIGI P249LCT-ND; Tolerance: 1%; Type: resistor; VPC: 1/16W; Vendor: Panasonic
R50 = RESISTOR: RES 95.3K OHM 1/10W 1% 0402 SMD; Manufacturer: Panasonic; P/D_NUM: ERJ-2RKF9532X; Part Number: ERJ-2RKF9532X; SOURCE: DIGI P95.3KLCT-ND; Tolerance: 1%
R54 = PAS,R,large: RES 2K OHM 1/10W 1% 0402 SMD; Family: passive; Index PN: 680; Lead Style: SMT; MFG: Panasonic; Manufacturer: Panasonic; Material: chip; P/D_NUM: ERJ-2RKF2001X; Part Number: ERJ-2RKF2001X; Power: 1/16W; SOURCE: DIGI P2.00KLCT-ND; Tolerance: 1%; Type: resistor; VPC: 1/16W; Vendor: Panasonic
R57 = PAS,R,large: RES 620 OHM 1/10W 1% 0402 SMD; Family: passive; Index PN: 680; Lead Style: SMT; MFG: Panasonic; Manufacturer: Panasonic; Material: chip; P/D_NUM: ERJ-2RKF6200X; Part Number: ERJ-2RKF6200X; Power: 1/16W; SOURCE: DIGI P620LCT-ND; Tolerance: 1%; Type: resistor; VPC: 1/16W; Vendor: Panasonic
R59 = RESISTOR: RES 274K OHM 1/10W 1% 0402 SMD; Manufacturer: Panasonic; P/D_NUM: ERJ-2RKF2743X; Part Number: ERJ-2RKF2743X; SOURCE: DIGI P274KLCT-ND; TOLERANCE: 1%
R60 = RESISTOR: RES 107K OHM 1/10W 1% 0402 SMD; Manufacturer: KOA; P/D_NUM: ERJ-2RKF1073X; Part Number: ERJ-2RKF1073X; SOURCE: DIGI P107KLCT-ND; TOLERANCE: 1%
SW3 = SWITCH,PUSH_BUTTON_SPST: SWITCH TACTILE SPST-NO 0.05A 12V; Manufacturer: Omron; RATING: 12VDC; SOURCE: DIGI SW1021CT-ND
U10 = BQ24250RGET
U11 = TPS63036YFGR
U12 = TPS82671SIPT
U13 = TPS386596L33DGK
U14 = TPS81256SIPR
U15 U18 = SN74LV1T08: Source: MOUSER 595-SN74LV1T08DCKR
U16 = SN74LVC1G04DBV: IC SINGLE INVERTER GATE 5-SC70; MFG: Texas Instruments; Manufacturer: Texas Instruments; SOURCE: Mouser 595-SN74LV1T04DCKR
U17 = SN74LVC1G32: IC GATE OR 1CH 2-INP SC-70-5; MFG: Texas Instruments; Manufacturer: Texas Instruments; SOURCE: DIGI 296-37202-1-ND
U19 = DMC2990UDJ: IC COMPLEMENTARY PAIR MOSFET; Manufacturer: Texas Instruments; Mfr: Texas Instruments; Source: DIGI DMC2990UDJ-7DICT-ND; Vendor: DIGI DMC2990UDJ-7DICT-ND

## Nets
GND: C1.2 C2.2 C3.2 C4.2 C5.2 C6.2 C7.2 C8.2 C10.2 C11.2 C12.2 C13.2 C14.2 C15.2 C17.1 C18.1 C19.2 C20.2 C21.2 C22.2 C23.2 C24.2 C25.2 C26.2 C27.2 C28.2 C29.1 C30.1 C32.2 C33.2 C34.2 C35.2 C36.2 C37.2 C38.2 C39.2 C40.2 C41.2 C42.2 C43.2 C44.2 C45.2 C46.2 C47.2 C48.2 C49.2 C50.2 C51.2 C52.2 C53.2 C54.1 C55.2 C56.2 C57.2 C58.2 C59.2 C60.2 C61.2 C62.2 C64.1 C65.2 C66.2 C67.2 C68.2 C69.2 C70.2 C71.1 C72.1 C73.2 C74.2 C75.1 C76.2 C77.1 C78.2 C79.2 C80.1 C81.2 C82.2 C83.2 C84.2 C85.1 C86.2 C87.1 C88.1 F1.2 J1.5 J2.1 J2.7 J2.12 J2.15 J2.16 J3.2 J3.9 J3.11 J3.12 J4.3 J4.5 J4.9 J5.5(P5) J5.6(P6) J5.9(P9) J5.10(P10) J5.19(P19) J5.20(P20) J5.33(P33) J5.34(P34) J5.43(P43) J5.44(P44) J5.49(P49) J5.50(P50) J5.59(P59) J5.60(P60) J5.69(P69) J5.70(P70) J5.79(P79) J5.80(P80) J6.2 J7.2 P1.6(VSS) P1.10(GND_CD) R8.1(N1) R9.1(N1) R12.2(N2) R13.2(N2) R21.1(N1) R31.1(N1) R41.2 R46.1(N1) R47.2(N2) R48.1(N1) R49.1(N1) R51.1(N1) R54.1(N1) R55.2(N2) R58.2 R60.2 SW1.2 SW2.2 SW3.2 U1.A1(GND) U1.A2(GND) U1.A18(GND) U1.A19(GND) U1.B1(GND) U1.B19(GND) U1.D18(GNDX2) U1.F10(GND) U1.G4(GNDA) U1.G5(VREFAn) U1.H10(GND) U1.H11(GND) U1.H12(GND) U1.J11(GND) U1.J12(GND) U1.K6(GND) U1.K9(GND) U1.K10(GND) U1.K13(GND) U1.K14(GND) U1.L8(GND) U1.L9(GND) U1.M8(GND) U1.M9(GND) U1.M10(GND) U1.N10(GND) U1.P16(GND) U1.R17(GND) U1.R18(GNDX) U1.V1(GND) U1.W1(GND) U1.W2(GND) U2.A1(VSS1) U2.A3(VSSQ1) U2.B7(VSSQ2) U2.C3(VSSQ3) U2.D7(VSSQ4) U2.E3(VSS2) U2.J1(VSS3) U3.4(GND) U4.9(GND) U4.17(THERMAL_PAD) U5.5(GND05) U5.7(GND07) U5.9(GND09) U5.13(GND13) U5.15(GND15) U5.17(GND17) U5.25(GNDPAD25) U5.26(GNDPAD26) U5.27(GNDPAD27) U5.28(GNDPAD28) U5.29(GNDPAD29) U5.30(GNDPAD30) U5.31(GNDPAD31) U5.32(GNDPAD32) U5.33(GNDPAD33) U6.B2(GND) U6.C1(ADR0) U6.D1(ADR1) U7.B2(GND) U9.7(GND) U9.9(3A) U9.10(3B) U9.12(4A) U9.13(4B) U9.15(THERMAL_PAD) U10.4(AGND) U10.15(PGND1) U10.16(PGND2) U10.25(PPAD) U11.B2(PS/SYNC) U11.C2(GND) U12.B1(MODE) U12.C1(GND1) U12.C2(GND2) U12.C3(GND3) U13.5(GND) U14.A1(GND1) U14.A2(GND2) U14.B1(GND3) U15.3(GND) U16.3(GND) U17.3(GND) U18.3(GND) U19.1(S1)
GND_EARTH: MH1.1 MH2.1 MH3.1 P1.9(GND9) P1.11(GND11) P1.12(GND12) P1.14(GND14) P1.15(GND15) P1.16(GND16) R58.1 SW1.3 SW2.3 SW3.3
ANT_PAD: E1.2
BAT_V_SW: R54.2(N2) R57.1(N1) U1.A4(PD4_AIN7)
BAT_VSENSE_EN: R55.1(N1) U1.B4(PD5_O) U19.2(G1)
BATTERY_THERMISTOR: J7.1 R44.2(N2) R47.1(N1) U10.9(TS)
BC_CSZ: R8.2(N2) U1.H4(PQ2_O) U10.1(CEz)
BC_EN1: R1.1(N1) U1.E2(PQ1_O) U10.2(EN1)
BC_EN2: R9.2(N2) U1.E3(PQ0_O) U10.3(EN2)
BC_INT: R4.1(N1) U1.W12(PQ5_I) U10.8(INT)
BC_SCL: R2.1(N1) U1.V3(PA0_I2C9SCL) U10.6(SCL)
BC_SDA: R3.1(N1) U1.W3(PA1_I2C9SDA) U10.5(SDA)
BT1P8_CTS: U4.6(A5) U5.4(HCI_RTS)
BT1P8_nSHUTD: R13.1(N1) U4.7(A6) U5.16(nSHUTD)
BT1P8_RTS: U4.3(A2) U5.1(HCI_CTS)
BT1P8_RX: U4.5(A4) U5.2(HCI_TX)
BT1P8_SLOW_CK: U4.1(A1) U5.8(SLOW_CLK_IN)
BT1P8_TX: U4.4(A3) U5.3(HCI_RX)
BT_ANT: C18.2 E1.1 L3.2
BT_ANTENNA: C17.2 L3.1 U5.14(BT_ANT)
BT_CTS: U1.B12(PP5_U3CTS) U4.11(B5)
BT_nSHUTD: R12.1(N1) U1.T2(PH5_O) U4.10(B6)
BT_RTS: U1.D8(PP4_U3RTS) U4.14(B2)
BT_RX: U1.C8(PJ0_U3RX) U4.12(B4)
BT_SLOW_CK: U1.C12(PP3_RTCCLK) U4.16(B1)
BT_TX: U1.E7(PJ1_U3TX) U4.13(B3)
CSZ: J2.5 R14.1
CSZP: R14.2 U1.C6(PB4_SSI1FSS)
DATAEN_CMD: R38.1(N1) U1.N1(PJ6_LCDAC) U9.1(1A)
DATAEN_CMD_B: J5.47(P47) R34.2(N2) R38.2(N2)
DIN: J2.8 R16.1
DINP: R16.2 U1.A5(PE4_SSI1XDAT0_TX)
DLPC_HOST_IRQ: J5.23(P23) R37.1(N1) U1.M3(PQ7_I)
DLPC_XLAT0_TIVA: J5.39(P39) U1.D6(PP0_I)
DLPC_XLAT1_TIVA: J5.41(P41) U1.D7(PP1_I)
DOUT_S: J2.9 U1.B5(PE5_SSI1XDAT1_RX)
DRDYZ: J2.10 U1.B13(PP2_I)
EN: R52.1(N1) R53.2(N2) U11.A2(EN) U14.B2(EN)
FLASH_DI_TIVA: J5.25(P25) U1.K17(PG4_SSI2XDAT1_RX)
HSYNC_CS: J5.48(P48) U1.N2(PR2_LCDLP)
HUM_DRDYz: R18.1(N1) U1.A8(PP7_I) U6.D2(DRDYz)
HUM_SCL: R20.1(N1) U1.F2(PB6_I2C6SCL) U6.A1(SCL)
HUM_SDA: R19.1(N1) U1.F1(PB7_I2C6SDA) U6.A2(SDA)
LI-Ion_BATTERY: C71.2 J6.1 R56.2(N2) U10.11(BAT1) U10.12(BAT2) U19.4(S2)
mSD_CARD_DET: P1.13(MSD_CARD_DET) R7.1(N1) U1.A13(PQ4_I)
mSD_CLK: P1.5(CLK) U1.T7(PF3_SSI3CLK)
mSD_CSz: P1.2(CSz) R5.1(N1) U1.W6(PF2_SSI3FSS)
mSD_DI: P1.3(DI) U1.V6(PF1_SSI3XDAT0)
mSD_DO: P1.7(DO) U1.U6(PF0_SSI3DAT1)
OSC0: C87.2 U1.E19(OSC0) Y2.1
P1P8V: C24.1 C56.1 C61.1 C75.2 J5.11(P11) J5.12(P12) R43.1 U7.A1(Vin) U12.A1(VOUT)
P1P8V_BT: C13.1 C15.1 C20.1 R11.2(N2) U4.2(VCCA) U5.18(VDD_IO) U7.A2(Vout)
P3P3V: C1.1 C2.1 C3.1 C4.1 C5.1 C6.1 C7.1 C8.1 C10.1 C11.1 C12.1 C19.1 C22.1 C23.1 C25.1 C28.1 C33.1 C34.1 C35.1 C36.1 C37.1 C38.1 C39.1 C40.1 C41.1 C42.1 C43.1 C44.1 C45.1 C46.1 C47.1 C48.1 C49.1 C50.1 C55.1 C57.1 C60.1 C68.1 C69.1 C70.1 C85.2 C86.1 J2.3 J3.1 J4.1 J5.7(P7) J5.8(P8) P1.4(VDD) R1.2(N2) R2.2(N2) R3.2(N2) R4.2(N2) R5.2(N2) R6.2(N2) R7.2(N2) R17.2(N2) R18.2(N2) R19.2(N2) R20.2(N2) R22.2(N2) R23.2(N2) R24.2(N2) R25.2(N2) R26.2(N2) R27.2(N2) R28.2(N2) R32.2(N2) R35.2(N2) R36.2(N2) R37.2(N2) R40.1 R45.1(N1) U1.F3(VDDA) U1.F4(VREFAp) U1.G10(VDD) U1.H9(VDD) U1.J8(VDD) U1.J9(VDD) U1.J10(VDD) U1.K7(VDD) U1.K8(VDD) U1.K11(VDD) U1.K12(VDD) U1.L10(VDD) U1.L11(VDD) U1.L12(VDD) U1.M11(VDD) U1.M12(VDD) U1.N16(VDD) U1.P10(VDD) U1.P17(VDD) U2.A7(VDDQ1) U2.A9(VDD1) U2.B3(VDDQ2) U2.C7(VDDQ3) U2.D3(VDDQ4) U2.E7(VDD2) U2.J9(VDD3) U4.15(VCCB) U5.12(VDD_IN) U6.B1(VDD) U9.14(VCC) U11.D1(VOUT) U13.4(SENSE1)
P5P0V: C21.1 C80.2 J2.2 R50.1 U14.A3(VOUT0) U14.B3(VOUT1) U14.C3(VOUT2)
P_LDO_V: C72.2 R42.2(N2) R44.1(N1) U10.24(LDO)
PAD_INTz: J5.29(P29) U17.2(B)
PAD_RSTz: J5.31(P31) U15.1(A)
PAD_RSTz_P3P3V: J5.28(P28) U1.U15(PQ6_I)
PCLK: J5.45(P45) U1.N5(PR0_LCDCP)
PDATA_00: J5.51(P51) U1.D13(PS1_LCDDATA21)
PDATA_01: J5.52(P52) U1.E18(PT2_LCDDATA18)
PDATA_02: J5.53(P53) U1.F18(PJ4_LCDDATA16)
PDATA_03: J5.54(P54) U1.P3(PR4_LCDDATA00)
PDATA_04: J5.55(P55) U1.P2(PR5_LCDDATA01)
PDATA_05: J5.56(P56) U1.U8(PF7_LCDDATA02)
PDATA_06: J5.57(P57) U1.V8(PR3-LCDDATA03)
PDATA_07: J5.58(P58) U1.W9(PR6_LCDDATA04)
PDATA_08: J5.61(P61) U1.B14(PS2_LCDDATA22)
PDATA_09: J5.62(P62) U1.F17(PT3_LCDDATA19)
PDATA_10: J5.63(P63) U1.R10(PR7_LCDDATA05)
PDATA_11: J5.64(P64) U1.V9(PS4_LCDDATA06)
PDATA_12: J5.65(P65) U1.T13(PS5_LCDDATA07)
PDATA_13: J5.66(P66) U1.U10(PS6_LCDDATA08)
PDATA_14: J5.67(P67) U1.R13(PS7_LCDDATA09)
PDATA_15: J5.68(P68) U1.W10(PT0_LCDDATA10)
PDATA_16: J5.71(P71) U1.A14(PS3_LCDDATA23)
PDATA_17: J5.72(P72) U1.D12(PS0_LCDDATA20)
PDATA_18: J5.73(P73) U1.E17(PJ5_LCDDATA17)
PDATA_19: J5.74(P74) U1.V10(PT1_LCDDATA11)
PDATA_20: J5.75(P75) U1.U12(PN7_LCDDATA12)
PDATA_21: J5.76(P76) U1.T12(PN6_LCDDATA13)
PDATA_22: J5.77(P77) U1.H17(PJ2_LCDDATA14)
PDATA_23: J5.78(P78) U1.F16(PJ3_LCDDATA15)
PROJ_ON: J5.36(P36) R31.2(N2) U1.K5(PJ7_O) U15.2(B)
PS_EN: R52.2(N2) U18.4(Y)
SCLK: J2.6 R15.1
SCLKP: R15.2 U1.B6(PB5_SSI1CLK)
SDR_AD00: U1.P4(PH0_EPI0S0) U2.A8(DQ0) U2.H7(A0)
SDR_AD01: U1.R2(PH1_EPI0S1) U2.B9(DQ1) U2.H8(A1)
SDR_AD02: U1.R1(PH2_EPI0S2) U2.B8(DQ2) U2.J8(A2)
SDR_AD03: U1.T1(PH3_EPI0S3) U2.C9(DQ3) U2.J7(A3)
SDR_AD04: U1.K3(PC7_EPI0S4) U2.C8(DQ4) U2.J3(A4)
SDR_AD05: U1.L2(PC6~{_}EPI0S5) U2.D9(DQ5) U2.J2(A5)
SDR_AD06: U1.M1(PC5_EPI0S6) U2.D8(DQ6) U2.H3(A6)
SDR_AD07: U1.M2(PC4_EPI0S7) U2.E9(DQ7) U2.H2(A7)
SDR_AD08: U1.V5(PA6_EPI0S8) U2.E1(DQ8) U2.H1(A8)
SDR_AD09: U1.R7(PA7_EPI0S9) U2.D2(DQ9) U2.G3(A9)
SDR_AD10: U1.T14(PG1_EPI0S10) U2.D1(DQ10) U2.H9(A10)
SDR_AD11: U1.N15(PG0_EPI0S11) U2.C2(DQ11) U2.G2(A11)
SDR_AD12: U1.L19(PM3_EPI0S12) U2.C1(DQ12) U2.G1(A12)
SDR_AD13: U1.L18(PM2_EPI0S13) U2.B2(DQ13) U2.G7(BA0)
SDR_AD14: U1.K19(PM1_EPI0S14) U2.B1(DQ14) U2.G8(BA1)
SDR_AD15: U1.K18(PM0_EPI0S15) U2.A2(DQ15)
SDR_CASz: U1.G18(PL2_EPI0S18) U2.F7(CASz)
SDR_CKE: U1.B10(PN3_EPI0S30) U2.F3(CKE)
SDR_CLK: U1.V17(PK5_EPI0S31) U2.F2(CLK)
SDR_CSz: U1.A11(PN2_EPI0S29) U2.G9(CSz)
SDR_LDQM: U1.G16(PL0_EPI0S16) U2.E8(LDQM)
SDR_RASz: U1.J18(PL3_EPI0S19) U2.F8(RASz)
SDR_UDQM: U1.H19(PL1_EPI0S17) U2.F1(UDQM)
SDR_WEz: U1.B17(PB3_EPI0S28) U2.F9(WEz)
SSI0CLK_U4RX: J3.3 U1.T6(PA2_SSI0CLK_U4RX)
SSI0FSS_U4TX: J3.4 U1.U5(PA3_SSI0FSS_U4TX)
SSI0XDAT0: J3.5 U1.V4(PA4_SSI0XDAT0)
SSI0XDAT1: J3.6 U1.W4(PA5_SSI0XDAT1)
SW_ON/OFF: C27.1 J3.10 R28.1(N1) SW2.1 U1.U18(WAKEz)
SW_SCAN: C26.1 R27.1(N1) SW1.1 U1.M4(PQ3_I_Scan)
SYNCZ: J2.4 U1.U2(PH6_O)
SYS_PWR: C58.1 C59.1 C64.2 C65.1 C66.1 C67.1 C73.1 C74.1 C76.1 C78.1 C79.1 C81.1 C82.1 C83.1 C84.1 J5.1(P1) J5.2(P2) J5.3(P3) J5.4(P4) L2.2 R53.1(N1) U10.13(SYS1) U10.14(SYS2) U11.A1(VIN) U12.A2(VIN0) U12.A3(VIN1) U12.B2(EN) U13.8(VCC) U14.C1(VIN0) U14.C2(VIN1) U15.5(VCC) U16.5(VCC) U17.5(VCC) U18.2(B) U18.5(VCC)
TDRDYZ: J2.14 U1.B8(PP6_I)
TIVA_DATAEN_MASK: U1.H3(PE0_O) U9.2(1B)
TIVA_EXP_I2C_SCL: J5.37(P37) R25.1(N1) U1.D2(PD2_I2C8_SCL)
TIVA_EXP_I2C_SDA: J5.35(P35) R26.1(N1) U1.D1(PD3_I2C8_SDA)
TIVA_FLASH_CLK: J5.26(P26) U1.U14(PG7_SSI2CLK)
TIVA_FLASH_CSz: J5.24(P24) R17.1(N1) U1.V12(PG6_SSI2FSS)
TIVA_FLASH_DO: J5.27(P27) U1.K15(PG5_SSI2XDAT0_TX)
TIVA_IIC0_SCL: J5.32(P32) R35.1(N1) U1.V11(PG2_I2C2SCL)
TIVA_IIC0_SDA: J5.30(P30) R36.1(N1) U1.M16(PG3_I2C2SDA)
TIVA_RESETz: J4.10 R45.2(N2) U1.P18(RESETz) U13.6(RESETZ)
TIVA_TCK: J4.4 U1.B15(PC0_TCK)
TIVA_TDI: J4.8 U1.D14(PC2_TDI)
TIVA_TDO: J4.6 U1.C14(PC3_TDO)
TIVA_TMS: J4.2 U1.C15(PC1_TMS)
TIVA_TRIG_IN_0: J5.38(P38) U1.G1(PE2_O)
TIVA_TRIG_IN_1: J5.40(P40) U1.G2(PE3_O)
TIVA_TRIG_SEL: J5.42(P42) U1.B2(PD7_O)
TIVA_VSYNC_MASK: U1.H2(PE1_O) U9.5(2B)
TSCL: J2.13 U1.C2(PD0_I2C7SCL)
TSDA: J2.11 U1.C1(PD1_I2C7SDA)
U4CTS: J3.8 U1.K2(PK3_U4CTS)
U4RTS: J3.7 U1.K1(PK2_U4RTS)
USB_DAT_N: J1.2 U1.B18(PL7_USB0DM) U3.2(D-)
USB_DAT_P: J1.3 U1.C18(PL6_USBDP) U3.1(D+)
USB_ID: J1.4 U1.A16(PB0_USB0ID) U3.3(ID)
USB_VBUS: C14.1 C62.1 J1.1 R59.1 U1.B16(PB1_USB0VBUS) U3.6(VBUS) U10.19(Vin)
VSYNC_WE: R39.1(N1) U1.N4(PR1_LCDFP) U9.4(2A)
VSYNC_WE_B: J5.46(P46) R33.2(N2) R39.2(N2)
XOSC0: C29.2 U1.T18(XOSC0) Y1.1
XOSC1: C30.2 U1.T19(XOSC1) Y1.2
N42370442: R48.2(N2) U10.22(ILIM)
N42370449: R49.2(N2) U10.10(ISET)
N42370456: C77.2 U10.20(PMID)
N42417768: C63.2 L2.1 U10.17(SW1) U10.18(SW2)
N42417797: C63.1 U10.21(BOOT)
N42420916: R59.2 R60.1 U10.23(VDPM)
N42420946: D4.2(C) U10.7(STAT)
N42420948: D4.1(A) R42.1(N1)
N42627229: L1.1 U11.B1(L1)
N42627251: L1.2 U11.C1(L2)
N42627428: R43.2 R46.2(N2) U13.2(SENSE3) U13.3(SENSE2)
N42627452: R50.2 R51.2(N2) U13.1(SENSE4)
N42627469: SW3.1 U13.7(MRZ)
N42627511: R40.2 R41.1 U11.D2(FB)
N43128043: U17.4(Y) U18.1(A)
N43128052: U16.4 U17.1(A)
N43142748: U15.4(Y) U16.2
N43167198: R34.1(N1) U9.3(1Y)
N43167201: R33.1(N1) U9.6(2Y)
N43219788: C51.1 C52.1 C53.1 C54.2 U1.E10(VDDC) U1.H16(VDDC)
N43219848: C32.1 R32.1(N1) U1.P19(VBAT)
N43219986: D3.1(A) R24.1(N1)
N43219998: D2.1(A) R23.1(N1)
N43220038: D1.1(A) R22.1(N1)
N43220044: D3.2(C) U1.W7(PF5__On/Off)
N43220071: D2.2(C) U1.V2(PH7_O_Bluetooth)
N43220075: D1.2(C) U1.H18(PL4_O_Scan)
N43273215: F1.1 J1.6 J1.7 J1.8 J1.9
N43274901: R21.2(N2) U1.A17(PB2_O) U7.B1(ON)
N43275105: R11.1(N1) U4.8(OE)
N43275134: P1.8(nIRQ) R6.1(N1)
N43328704: R56.1(N1) U19.5(G2) U19.6(D1)
N43328728: R57.2(N2) U19.3(D2)
N43392226: R30.1(N1) U1.D19(OSC1)
N43392629: C88.2 R30.2(N2) Y2.3

Not connected (* = marked no-connect by the designer): J4 7*; J5 13(P13)* 14(P14)* 15(P15)* 16(P16)* 17(P17)* 18(P18)* 21(P21)* 22(P22)*; P1 1(NC)*; U1 M17(HIBz)*; U2 E2(NC1)*; U3 5(NC)*; U5 6(NC06)* 10(NC10)* 11(NC11)* 19(AUD_IN)* 20(AUD_OUT)* 21(AUD_CLK)* 22(AUD_FSYNC)* 23(IO1)* 24(TX_DBG)*; U9 8(3Y)* 11(4Y)*; Y1 3*; Y2 2* 4*

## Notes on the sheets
sheet 1
- COMPUTER GENERATED DRAWING - DO NOT REVISE MANUALLY
- NOTES, UNLESS OTHERWISE SPECIFIED:
- REVISIONS
- REV
- DESCRIPTION
- DATE
- APPROVED
- 1.
- The netname "V5P0V" represents connection to the +5.0V power buss.
- -
- Draft Release
- 07/24/2014
- HPC
- 2.
- The netname "V3P3V" represents connection to the +3.3V power buss
- 3.
- The netname "V1P8V" represents connection to the +1.8V power buss
- A
- ECO 2143344: REV A Release
- 4.
- The netname "USB_VBUS" represents connection to the +5.0V USB host power buss.
- 5.
- The netname "SYS_PWR" represents connection to the +4.5V power buss.
- 6.
- The netname "GND" represents connection to the ground plane.
- 7.
- A "Z" suffix on a signal name indicates an active low signal.
- 8.
- All components with designators "U*", "Q*", and "D*" are electrostatic discharge sensitive.
- 9.
- All resistor values are in ohms.
- 10.
- All capacitor values in microfarads unless otherwise specified.
- 7
- ???
- ???
sheet 2
- EXTERNAL MEMORY
- 2
- 7
sheet 3
- CHASSIS_GND
- 50 OHM TRACE
- Peripherals
- 3
- 7
sheet 4
- YELLOW
- BLUE
- GREEN
- CHASSIS_GND
- CHASSIS_GND
- Locate C85 & C86 as close
- to Pin F4 as possible
- TIVA POWER & MISC
sheet 5
- TIVA PARALLEL & MISC INTERFACES
- 5
- 7
sheet 6
- RED
- CHASSIS_GND
- POWER SUPPLIES
- 6
- 7
sheet 7
- Revision History
- Rev. -- : Draft Release ~ 07/24/2014
- Rev. A: ECO 2143344: ~ 04/??/2014
- Rev. A: (1) Added Thermal Pad Contacts to U4 and U9  08/21/2014 MR.
- (2) Added (3) 2-56 Mounting Holes.  08/21/2014 MR.
- (3) Added R58 0.1ohm resistor between chassis ground and common ground.  08/21/2014 MR.
- (4) Changed U1 part#TM4C1297NCZADI3 to TM4C1299NCZADI3 .  08/29/2014 MR.
- Rev. B: C13 Changed to DNI 10/19/2014 MR.
- C12 Changed to 1uF 10/19/2014 MR.
- C24 Changed to 1uF 10/19/2014 MR.
- U10 Changed SYS PWR connections to pin13 & pin14.10/19/2014 MR.
- C64 Changed positive connection to U10 pin13 & pin14  and negative connection to GND 10/19/2014 MR.
- U8 removed, replace with Y2 add C87 and C88. page4 10/22/2014 MR.
- Added R59 & R60 voltage divider at U10. page6 10/31/2014 MR.
- Rev. C: R26 and R26 Changed to DNI. 02/06/2015 PG.
- Changed U1 part#TM4C1299NCZADI3 to TM4C1297NCZADI3.  02/06/2015 PG.
- Changed R44 from DNI to 5.1k.  04/10/2015 MR.
- Rev. D: P1 device changed net connections on pin9(GND) and pin13(MD_CARD_DET).
- Schematic Revision History
